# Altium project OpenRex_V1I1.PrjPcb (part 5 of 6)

## Sheet [28] - PWR IN, MECH, DOC.SchDoc
size A2; DocumentNumber: 28; SheetNumber: 28; SheetTotal: 31
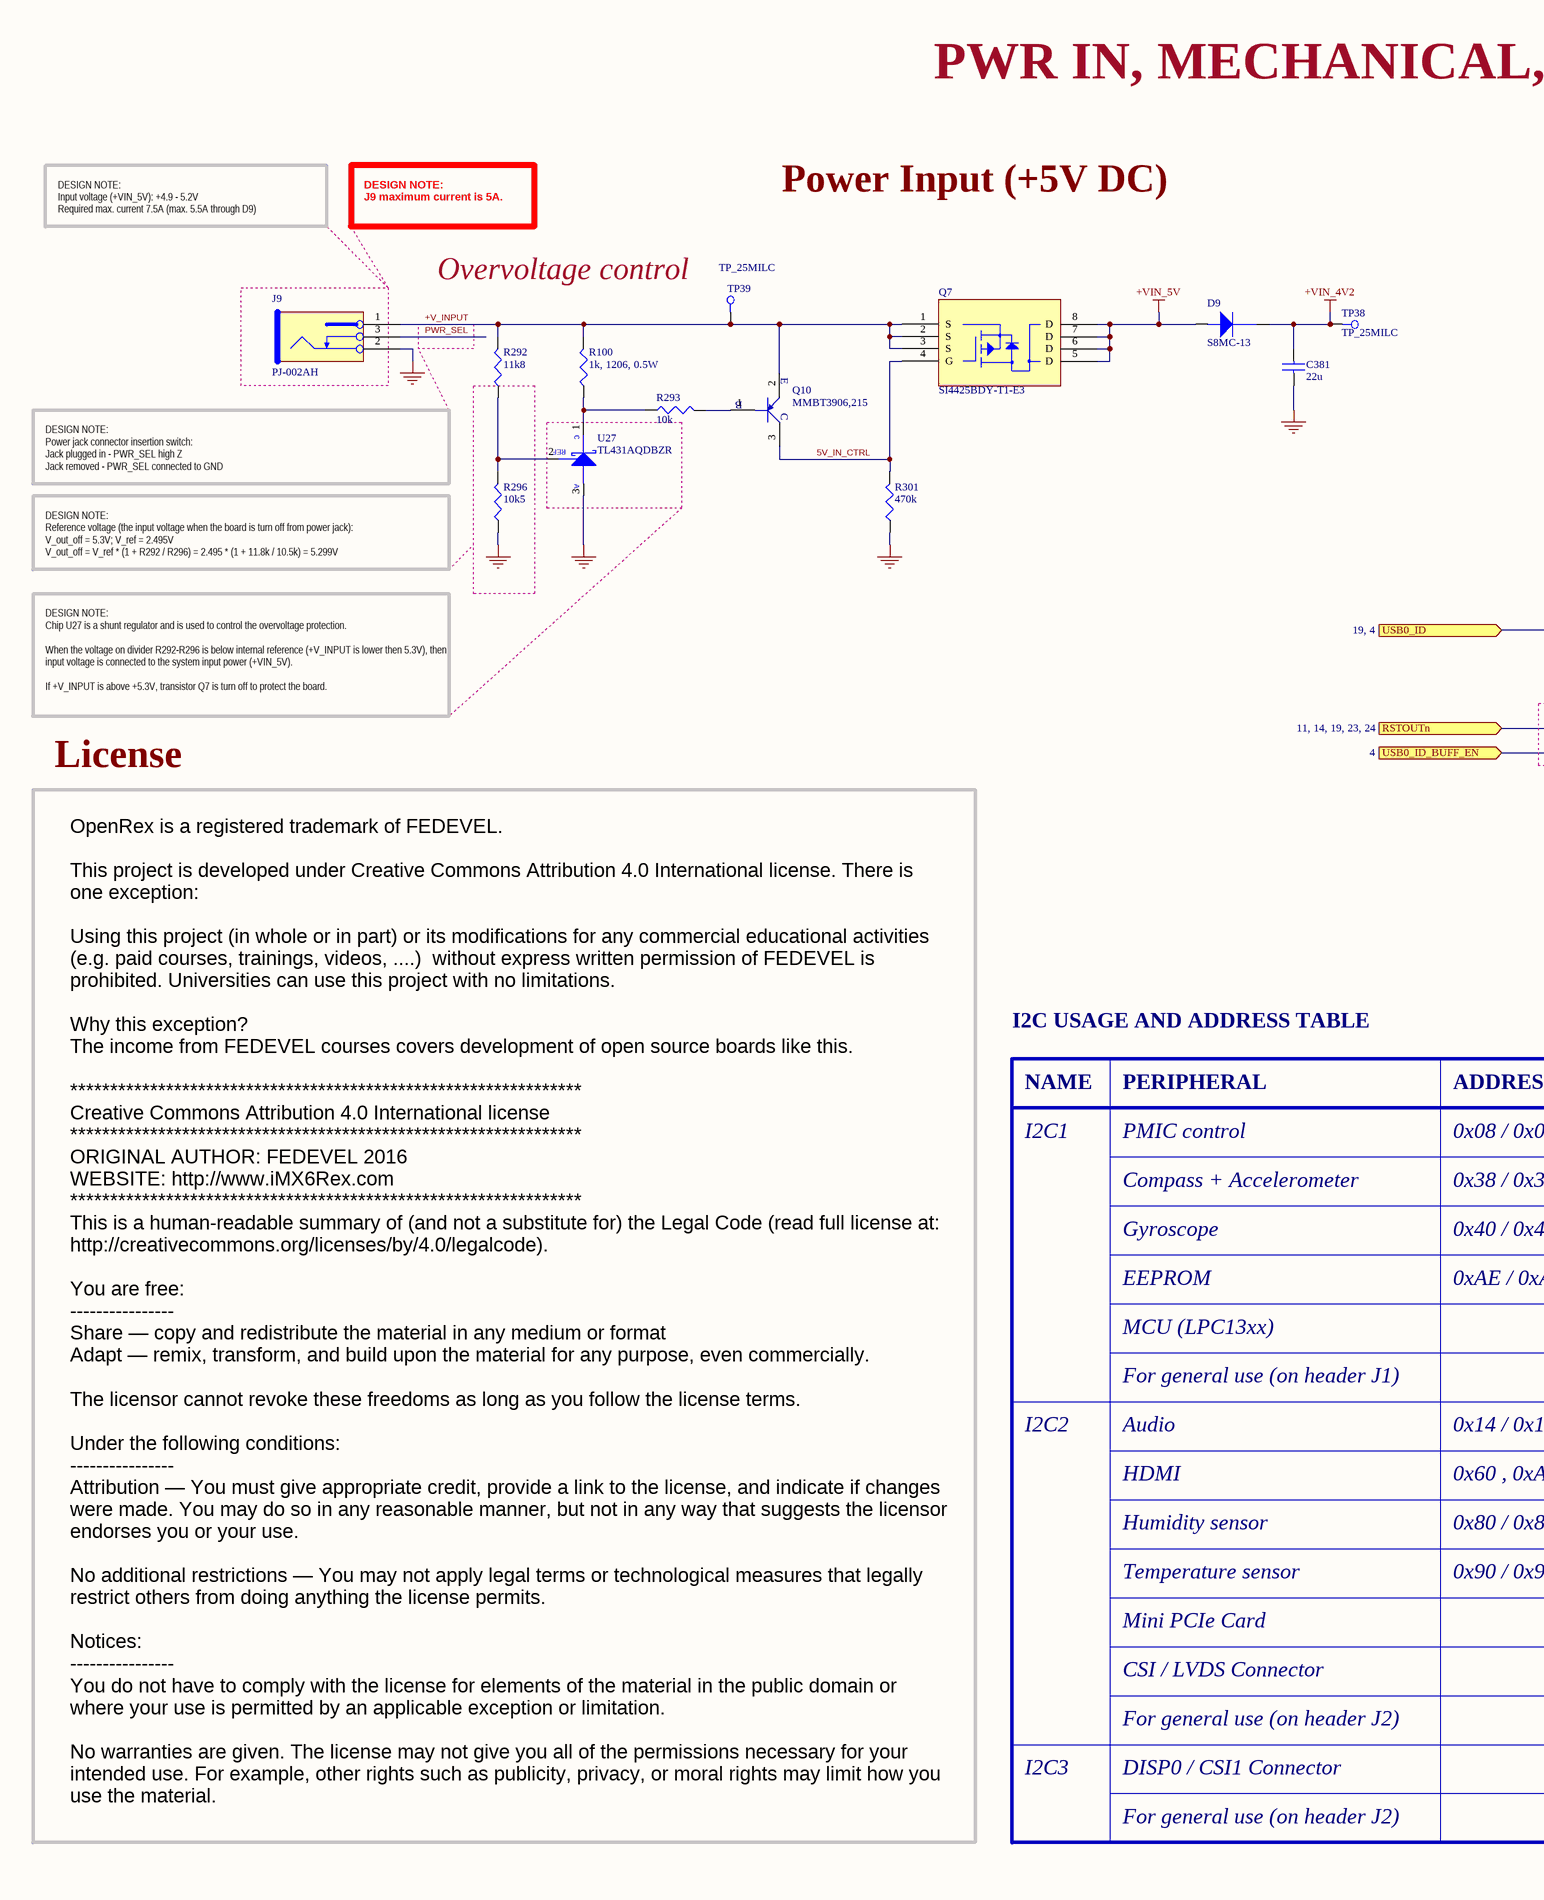
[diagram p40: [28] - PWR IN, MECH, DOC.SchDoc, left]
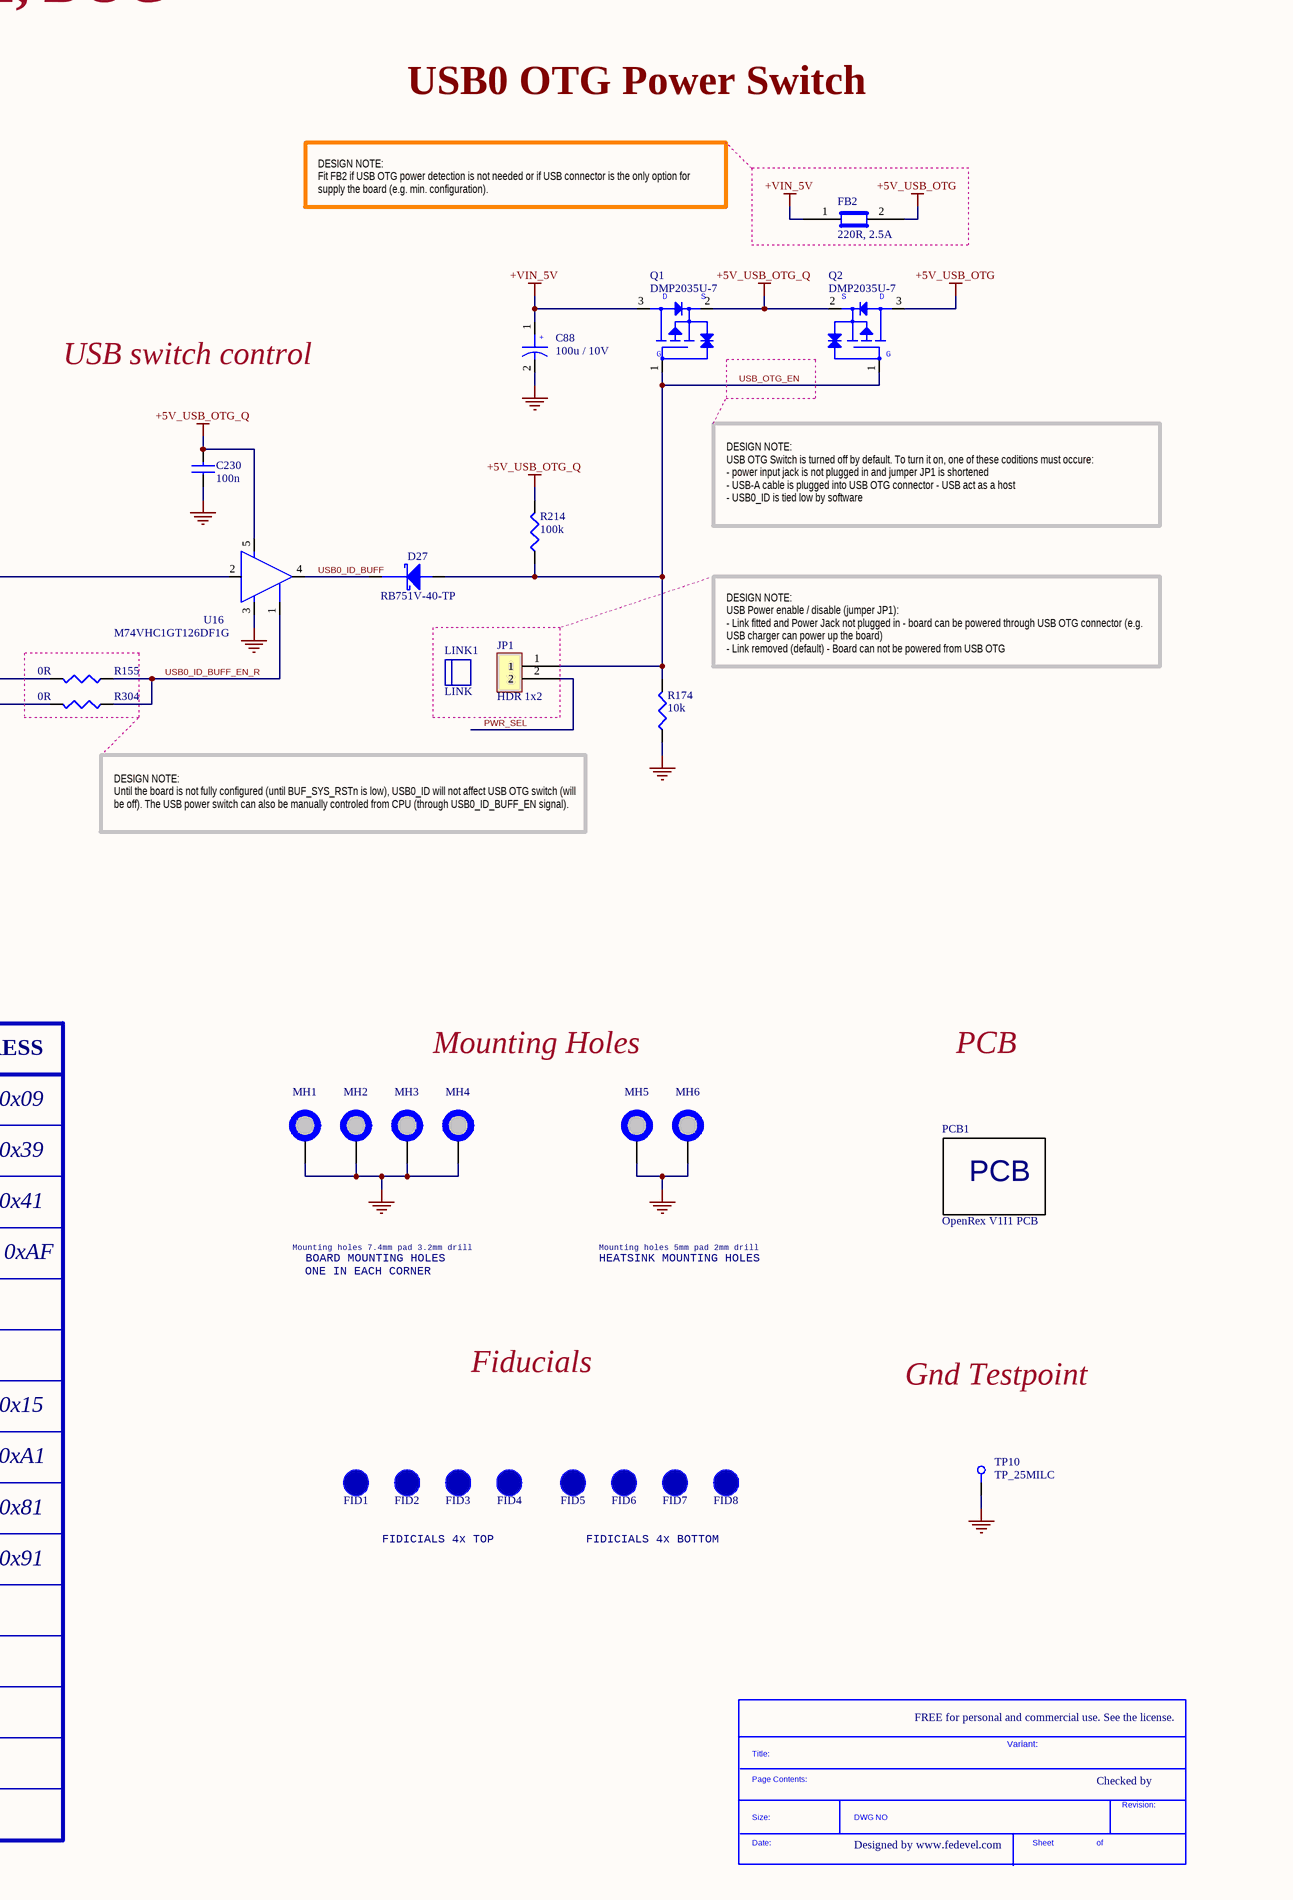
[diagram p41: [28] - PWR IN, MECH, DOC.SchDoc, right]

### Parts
(Parts that share a designator on the sheet are numbered #1, #2 ... from top to bottom, then left to right.)
*#24  SDTitleBlock  (value not drawn)  (graphical)
C88  100u / 10V  [C2312]
C230  100n  [C0402]
C381  22u  [C0603]
D9  S8MC-13  [SMC]
D27  RB751V-40-TP  [SOD323]
FB2  220R, 2.5A  [C0603]
FID1  FID_1MM_SMALL  [FID_40X52D]  (value not drawn)  (no BOM)
FID2  FID_1MM_SMALL  [FID_40X52D]  (value not drawn)  (no BOM)
FID3  FID_1MM_SMALL  [FID_40X52D]  (value not drawn)  (no BOM)
FID4  FID_1MM_SMALL  [FID_40X52D]  (value not drawn)  (no BOM)
FID5  FID_1MM_SMALL  [FID_40X52D]  (value not drawn)  (no BOM)
FID6  FID_1MM_SMALL  [FID_40X52D]  (value not drawn)  (no BOM)
FID7  FID_1MM_SMALL  [FID_40X52D]  (value not drawn)  (no BOM)
FID8  FID_1MM_SMALL  [FID_40X52D]  (value not drawn)  (no BOM)
J9  PJ-002AH  [POWER_JACK_5.5_2.1MM_NS_v1.1]
JP1  HDR 1x2  [HDR_1x2_2.54MM]
LINK1  LINK  (mechanical)
MH1  MH_7.4MMC_3.2MMD  [MH_7.4MMD_3.2MMD]  (value not drawn)  (no BOM)
MH2  MH_7.4MMC_3.2MMD  [MH_7.4MMD_3.2MMD]  (value not drawn)  (no BOM)
MH3  MH_7.4MMC_3.2MMD  [MH_7.4MMD_3.2MMD]  (value not drawn)  (no BOM)
MH4  MH_7.4MMC_3.2MMD  [MH_7.4MMD_3.2MMD]  (value not drawn)  (no BOM)
MH5  MH_5MMC_2MMD  [MH_5MMD_2MMD]  (value not drawn)  (no BOM)
MH6  MH_5MMC_2MMD  [MH_5MMD_2MMD]  (value not drawn)  (no BOM)
PCB1  OpenRex V1I1 PCB  (mechanical)
Q1  DMP2035U-7  [SOT-23-3-123]
Q2  DMP2035U-7  [SOT-23-3-123]
Q7  SI4425BDY-T1-E3  [8_SOIC_3.9MM]
Q10  MMBT3906,215  [SOT-23-3-123]
R100  1k, 1206, 0.5W  [R1206]
R155  0R  [R0402]
R174  10k  [R0402]
R214  100k  [R0402]
R292  11k8  [R0402]
R293  10k  [R0402]
R296  10k5  [R0402]
R301  470k  [R0402]
R304  0R  [R0402]
TP10  TP_25MILC  [TP_25C]  (no BOM)
TP38  TP_25MILC  [TP_25C]  (no BOM)
TP39  TP_25MILC  [TP_25C]  (no BOM)
U16  M74VHC1GT126DF1G  [SC70_5]
U27  TL431AQDBZR  [SOT-23-3-123]

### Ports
RSTOUTn (see 11, 14, 19, 23, 24), USB0_ID (see 19, 4), USB0_ID_BUFF_EN (in, see 4)

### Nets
+5V_USB_OTG: FB2.2 Q2.3
+5V_USB_OTG_Q: C230.2 Q1.2 Q2.2 R214.2 U16.5(VCC)
+VIN_4V2: C381.1 D9.1(Cathode) TP38.1
+VIN_5V: C88.1 D9.2(Anode) FB2.1 Q1.3 Q7.5(D) Q7.6(D) Q7.7(D) Q7.8(D)
GND: C88.2 C230.1 C381.2 J9.2 MH1.1 MH2.1 MH3.1 MH4.1 MH5.1 MH6.1 R174.1 R296.1 R301.1 TP10.1 U16.3(GND) U27.3(ANODE)
5V_IN_CTRL: Q7.4(G) Q10.3(C) R301.2
+V_INPUT: J9.1 Q7.1(S) Q7.2(S) Q7.3(S) Q10.2(E) R100.2 R292.2 TP39.1
PWR_SEL: J9.3 JP1.2
RSTOUTn: R155.2 ; port RSTOUTn
USB0_ID: U16.2(I) ; port USB0_ID
USB0_ID_BUFF: D27.1(cathode) U16.4(O)
USB0_ID_BUFF_EN: R304.2 ; port USB0_ID_BUFF_EN
USB0_ID_BUFF_EN_R: R155.1 R304.1 U16.1(OE#)
USB_OTG_EN: D27.2(ANODE) JP1.1 Q1.1 Q2.1 R174.2 R214.1
NetQ10_1: Q10.1(B) R293.2
NetR100_1: R100.1 R293.1 U27.1(cathode)
NetR292_1: R292.1 R296.2 U27.2(REF)

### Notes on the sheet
- PWR IN, MECHANICAL, DOC
- Power Input (+5V DC)
- USB0 OTG Power Switch
- DESIGN NOTE:
  Input voltage (+VIN_5V): +4.9 - 5.2V
  Required max. current 7.5A (max. 5.5A through D9)
- DESIGN NOTE:
  J9 maximum current is 5A.
- DESIGN NOTE:
  Fit FB2 if USB OTG power detection is not needed or if USB connector is the only option for supply the board (e.g. min. configuration).
- (near TP39) Overvoltage control
- USB switch control
- DESIGN NOTE:
  Power jack connector insertion switch:
  Jack plugged in - PWR_SEL high Z
  Jack removed - PWR_SEL connected to GND
- DESIGN NOTE:
  Reference voltage (the input voltage when the board is turn off from power jack):
  V_out_off = 5.3V; V_ref = 2.495V
  V_out_off = V_ref * (1 + R292 / R296) = 2.495 * (1 + 11.8k / 10.5k) = 5.299V
- DESIGN NOTE:
  USB OTG Switch is turned off by default. To turn it on, one of these coditions must occure:
  - power input jack is not plugged in and jumper JP1 is shortened
  - USB-A cable is plugged into USB OTG connector - USB act as a host
  - USB0_ID is tied low by software
- DESIGN NOTE:
  Chip U27 is a shunt regulator and is used to control the overvoltage protection.
  When the voltage on divider R292-R296 is below internal reference (+V_INPUT is lower then 5.3V), then input voltage is connected to the system input power (+VIN_5V).
  If +V_INPUT is above +5.3V, transistor Q7 is turn off to protect the board.
- DESIGN NOTE:
  USB Power enable / disable (jumper JP1):
  - Link fitted and Power Jack not plugged in - board can be powered through USB OTG connector (e.g. USB charger can power up the board)
  - Link removed (default) - Board can not be powered from USB OTG
- License
- DESIGN NOTE:
  Until the board is not fully configured (until BUF_SYS_RSTn is low), USB0_ID will not affect USB OTG switch (will be off). The USB power switch can also be manually controled from CPU (through USB0_ID_BUFF_EN signal).
- I2C USAGE AND ADDRESS TABLE
- NAME
- PERIPHERAL
- ADDRESS
- Mounting Holes
- PCB
- I2C1
- Compass + Accelerometer
- PMIC control
- 0x38 / 0x39
- 0x08 / 0x09
- Gyroscope
- 0x40 / 0x41
- EEPROM
- 0xAE / 0xAF
- Mounting holes 7.4mm pad 3.2mm drill
- BOARD MOUNTING HOLES
- ONE IN EACH CORNER
- HEATSINK MOUNTING HOLES
- Mounting holes 5mm pad 2mm drill
- MCU (LPC13xx)
- I2C2
- For general use (on header J1)
- Audio
- 0x14 / 0x15
- Fiducials
- Gnd Testpoint
- HDMI
- 0x60 , 0xA1
- Humidity sensor
- 0x80 / 0x81
- FIDICIALS 4x TOP
- FIDICIALS 4x BOTTOM
- Temperature sensor
- 0x90 / 0x91
- Mini PCIe Card
- CSI / LVDS Connector
- For general use (on header J2)
- FREE for personal and commercial use. See the license.
- I2C3
- DISP0 / CSI1 Connector
- Variant:
- Checked by
- OpenRex is a registered trademark of FEDEVEL.
  This project is developed under Creative Commons Attribution 4.0 International license. There is one exception:
  Using this project (in whole or in part) or its modifications for any commercial educational activities (e.g. paid courses, trainings, videos, ....)  without express written permission of FEDEVEL is prohibited. Universities can use this project with no limitations.
  Why this exception?
  The income from FEDEVEL courses covers development of open source boards like this.
  ****************************************************************
  Creative Commons Attribution 4.0 International license
  ****************************************************************
  ORIGINAL AUTHOR: FEDEVEL 2016
  WEBSITE: http://www.iMX6Rex.com
  ****************************************************************
  This is a human-readable summary of (and not a substitute for) the Legal Code (read full license at:
  http://creativecommons.org/licenses/by/4.0/legalcode).
  You are free:
  ----------------
  Share — copy and redistribute the material in any medium or format
  Adapt — remix, transform, and build upon the material for any purpose, even commercially.
  The licensor cannot revoke these freedoms as long as you follow the license terms.
  Under the following conditions:
  ----------------
  Attribution — You must give appropriate credit, provide a link to the license, and indicate if changes were made. You may do so in any reasonable manner, but not in any way that suggests the licensor endorses you or your use.
  No additional restrictions — You may not apply legal terms or technological measures that legally restrict others from doing anything the license permits.
  Notices:
  ----------------
  You do not have to comply with the license for elements of the material in the public domain or where your use is permitted by an applicable exception or limitation.
  No warranties are given. The license may not give you all of the permissions necessary for your intended use. For example, other rights such as publicity, privacy, or moral rights may limit how you use the material.
- Designed by www.fedevel.com

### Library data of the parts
C88 = TPSC107K010R0150: CAP TANT 100UF 10V 10% 2312; Manufacturer: AVX Corporation; Manufacturer Size Code: C; Capacitance: 100µF; ESR (Equivalent Series Resistance): 150 mOhm; Type: Molded; .Creator: MM
C230 = C1005X5R1H104K: CAP CER .10UF 50V X5R 10% 0402; Manufacturer: TDK Corporation; Capacitance: 0.1µF; Value: 100nF; .Checked PCB: used
C381 = C1608X5R0J226M080AC: CAP CER 22UF 6.3V 20% X5R 0603; Manufacturer: TDK Corporation; Capacitance: 22µF; .Creator: MM
D9 = S8MC-13: DIODE GEN PURP 1KV 8A SMC; Manufacturer: Diodes Incorporated; Diode Type: Standard; Voltage - DC Reverse (Vr) (Max): 1000V (1kV); Voltage - Forward (Vf) (Max) @ If: 985mV @ 8A; Speed: Standard Recovery >500ns, > 200mA (Io); Current - Reverse Leakage @ Vr: 10µA @ 1000V; Capacitance @ Vr, F: 40pF @ 4V, 1MHz; .Checked PCB: MM
D27 = RB751V-40-TP: DIODE SCHTKY 30MA 30V SOD-323; Manufacturer: Micro Commercial Co; Diode Type: Schottky; Voltage - Forward (Vf) (Max) @ If: 370mV @ 1mA; Speed: Small Signal =< 200mA (Io), Any Speed; Current - Reverse Leakage @ Vr: 500nA @ 30V; Capacitance @ Vr, F: 2pF @ 1V, 1MHz; .Checked PCB: used
FB2 = BLM18SG221TN1D: FERRITE CHIP 220 OHM 2500MA 0603; Manufacturer: Murata Electronics North America; Impedance @ Frequency: 220 Ohm @ 100MHz; DC Resistance (DCR): 40 mOhm Max; Filter Type: Differential Mode - Single; Number of Lines: 1; .Checked PCB: used
FID1-FID8 = FID_1MM_SMALL: Fiducial 40mil Diameter, 52mil Mask
J9 = PJ-002AH_v1.1: CONN PWR JACK 2.1X5.5MM HIGH CUR; Manufacturer: CUI Inc; .Checked PCB: MM; Mating connector: 2.1mm ID, 5.5mm OD; Gender: Male; Number of Positions/Contacts: 2 Conductors, 3 Contacts; Internal Switch(s): Single Switch, Normally Closed; Shielding: Unshielded; Voltage - Rated: 24VDC; Current Rating: 5A
JP1 = 68001-202HLF: BERGSTIK II .100" SR STRAIGHT; Manufacturer: FCI; Connector Type: Header, Unshrouded; Number of Positions: 2; Number of Positions Loaded: All; Pitch: 0.100" (2.54mm); .Checked PCB: used
LINK1 = QPC02SXGN-RC: CONN JUMPER SHORTING .100" GOLD; Manufacturer: Sullins Connector Solutions; Gender: Female Sockets; Number of Positions or Pins (Grid): 2 (1 x 2); Pitch: 0.100" (2.54mm); .Checked SCH: used
MH1-MH4 = MH_7.4MMC_3.2MMD: Mounting Hole 7.4mm Diameter, 3.2mm Drill; .Creator: MM
MH5 MH6 = MH_5MMC_2MMD: Mounting Hole 5mm Diameter, 2mm Drill; .Creator: MM
PCB1 = PCB_OpenRex_V1I1: .Creator: MM
Q1 Q2 = DMP2035U-7: MOSFET P-CH 20V 3.6A SOT-23; Manufacturer: Diodes Incorporated; FET Type: MOSFET P-Channel, Metal Oxide; FET Feature: Logic Level Gate; Current - Continuous Drain (Id) @ 25°C: 3.6A (Ta); Rds On (Max) @ Id, Vgs: 35 mOhm @ 4A, 4.5V; Vgs(th) (Max) @ Id: 1V @ 250µA; Gate Charge (Qg) @ Vgs: 15.4nC @ 4.5V; Input Capacitance (Ciss) @ Vds: 1610pF @ 10V; Power - Max: 810mW; .Checked PCB: MM
Q7 = SI4425BDY-T1-E3: MOSFET P-CH 30V 8.8A 8-SOIC; Manufacturer: Vishay Siliconix; FET Type: MOSFET P-Channel, Metal Oxide; FET Feature: Logic Level Gate; Current - Continuous Drain (Id) @ 25°C: 8.8A (Ta); Rds On (Max) @ Id, Vgs: 12 mOhm @ 11.4A, 10V; Vgs(th) (Max) @ Id: 3V @ 250µA; Gate Charge (Qg) @ Vgs: 100nC @ 10V; Power - Max: 1.5W; .Checked PCB: MM
Q10 = MMBT3906,215: TRANS PNP 40V 0.2A SOT23; Manufacturer: NXP Semiconductors; Current - Collector (Ic) (Max): 200mA; Vce Saturation (Max) @ Ib, Ic: 400mV @ 5mA, 50mA; DC Current Gain (hFE) (Min) @ Ic, Vce: 100 @ 10mA, 1V; Power - Max: 250mW; Frequency - Transition: 250MHz; .Checked PCB: MM
R100 = RNCP1206FTD1K00: RES SMD 1K OHM 1% 1/2W 1206; Manufacturer: Stackpole Electronics Inc; Power (Watts): 0.5W, 1/2W; Temperature Coefficient: ±100ppm/°C; .Checked PCB: MM
R155 R304 = RC0402JR-070RL: RES 0.0 OHM 1/16W 0402 SMD; Manufacturer: Yageo; Resistance (Ohms): 0.0; Power (Watts): 0.063W, 1/16W; Tolerance: Jumper; .Checked PCB: used
R174 R293 = RC0402FR-0710KL: RES 10.0K OHM 1/16W 1% 0402 SMD; Manufacturer: Yageo; Power (Watts): 0.063W, 1/16W; .Checked PCB: used; Temperature Coefficient: ±100ppm/°C
R214 = RMCF0402FT100K: RES 100K OHM 1/16W 1% 0402 SMD; Manufacturer: Stackpole Electronics Inc; Power (Watts): 0.063W, 1/16W; .Checked PCB: used; Temperature Coefficient: ±100ppm/°C
R292 = CRCW040211K8FKED: RES 11.8K OHM 1/16W 1% 0402 SMD; Manufacturer: Vishay Dale; Power (Watts): 0.063W, 1/16W; Temperature Coefficient: ±100ppm/°C; .Checked PCB: RF
R296 = CRCW040210K5FKED: RES 10.5K OHM 1/16W 1% 0402 SMD; Manufacturer: Vishay/Dale; Power (Watts): 0.063W, 1/16W; .Checked PCB: used; Temperature Coefficient: ±100ppm/°C
R301 = CRCW0402470KFKED: RES 470K OHM 1/16W 1% 0402 SMD; Manufacturer: Vishay Dale; Power (Watts): 0.063W, 1/16W; Temperature Coefficient: ±100ppm/°C; .Checked PCB: MM
TP10 TP38 TP39 = TP_25MILC: Test Point 25mil
U16 = M74VHC1GT126DF1G: IC BUFF CMOS LVL/SFTR N-I SOT353; Manufacturer: ON Semiconductor; Logic Type: Buffer/Line Driver, Non-Inverting; Number of Elements: 1; Current - Output High, Low: 8mA, 8mA; Voltage - Supply: 3 V ~ 5.5 V; .Checked PCB: MM
U27 = TL431AQDBZR: IC VREF SHUNT ADJ SOT23-3; Manufacturer: Texas Instruments; Output Type: Adjustable; Voltage - Output (Min/Fixed): 2.495V; Voltage - Output (Max): 36V; Current - Output: 100mA; Tolerance: ±1%; Current - Cathode: 700µA; .Checked PCB: MM

## Sheet [22] - SD CARD, SPI, FLASH, EEPROM,.SchDoc
size A2; DocumentNumber: 22; SheetNumber: 22; SheetTotal: 31
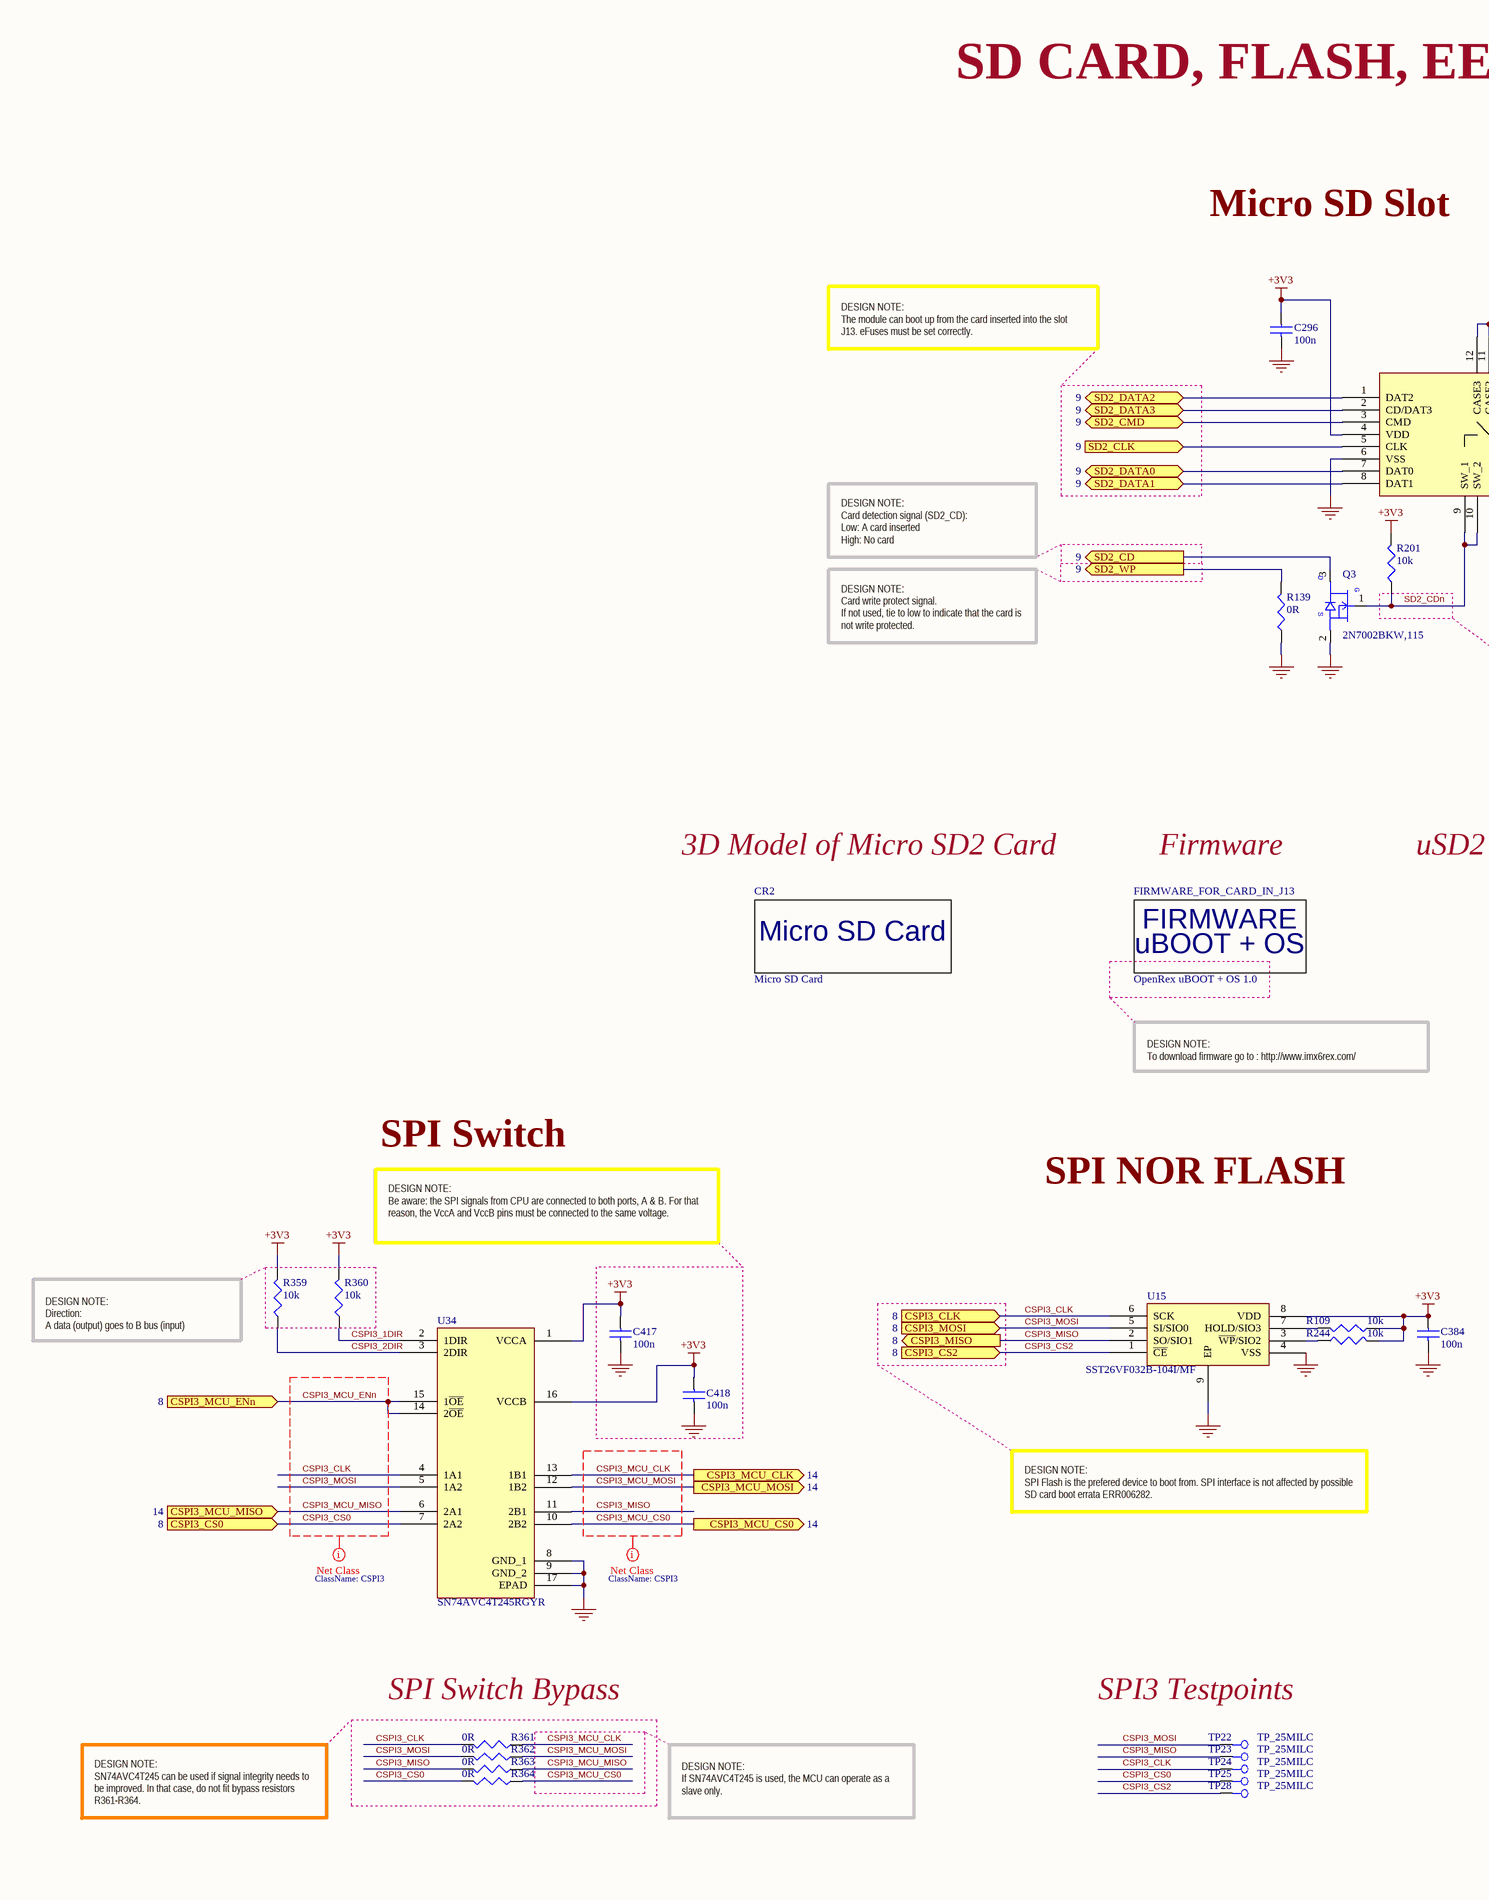
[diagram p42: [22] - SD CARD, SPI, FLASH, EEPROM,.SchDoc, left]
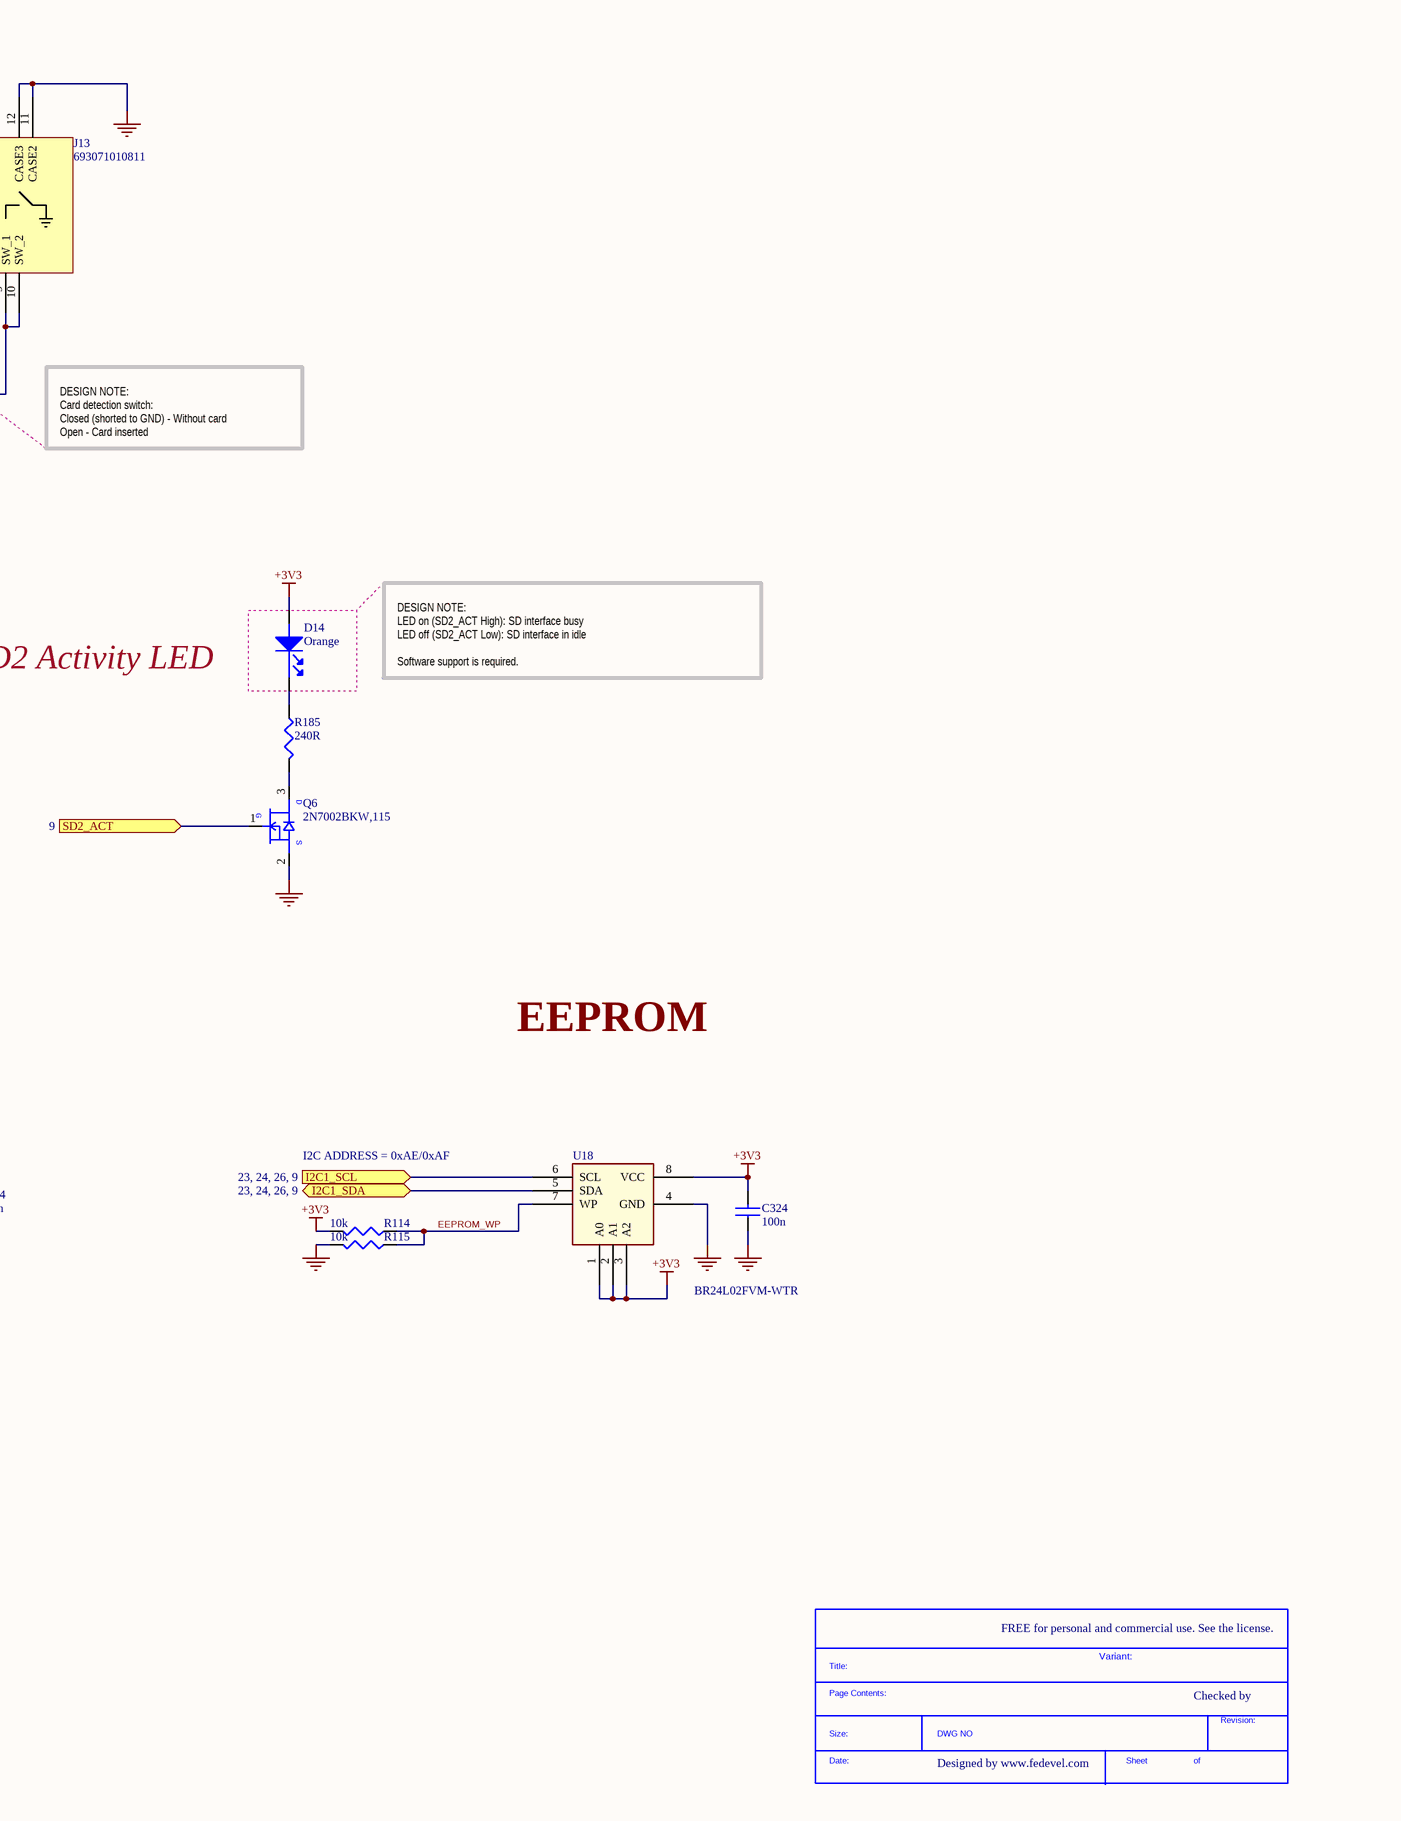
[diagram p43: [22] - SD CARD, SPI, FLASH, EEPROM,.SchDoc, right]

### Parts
(Parts that share a designator on the sheet are numbered #1, #2 ... from top to bottom, then left to right.)
*#25  SDTitleBlock  (value not drawn)  (graphical)
C296  100n  [C0402]
C324  100n  [C0402]
C384  100n  [C0402]
C417  100n  [C0402]
C418  100n  [C0402]
CR2  Micro SD Card  [Micro_SD_card]  (no BOM)
D14  Orange  [LED_0603]
FIRMWARE_FOR_CARD_IN_J13  OpenRex uBOOT + OS 1.0  (mechanical)
J13  693071010811  [693071010811]
Q3  2N7002BKW,115  [SC70_SOT323]
Q6  2N7002BKW,115  [SC70_SOT323]
R109  10k  [R0402]
R114  10k  [R0402]
R115  10k  [R0402]
R139  0R  [R0402]
R185  240R  [R0402]
R201  10k  [R0402]
R244  10k  [R0402]
R359  10k  [R0402]
R360  10k  [R0402]
R361  0R  [R0402]
R362  0R  [R0402]
R363  0R  [R0402]
R364  0R  [R0402]
TP22  TP_25MILC  [TP_25C]  (no BOM)
TP23  TP_25MILC  [TP_25C]  (no BOM)
TP24  TP_25MILC  [TP_25C]  (no BOM)
TP25  TP_25MILC  [TP_25C]  (no BOM)
TP28  TP_25MILC  [TP_25C]  (no BOM)
U15  SST26VF032B-104I/MF  [WSON8_6X5MM]
U18  BR24L02FVM-WTR  [MSOP8 _SMALLER]
U34  SN74AVC4T245RGYR  [RGY (R-PVQFN-N16)]

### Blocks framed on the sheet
SPI Switch Bypass: R361-R364

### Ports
CSPI3_CLK (see 8), CSPI3_CS0 (in, see 8), CSPI3_CS2 (in, see 8), CSPI3_MCU_CLK (out, see 14), CSPI3_MCU_CS0 (out, see 14), CSPI3_MCU_ENn (in, see 8), CSPI3_MCU_MISO (in, see 14), CSPI3_MCU_MOSI (out, see 14), CSPI3_MISO (out, see 8), CSPI3_MOSI (see 8), I2C1_SCL (see 23, 24, 26, 9), I2C1_SDA (bidir, see 23, 24, 26, 9), SD2_ACT (in, see 9), SD2_CD (out, see 9), SD2_CLK (in, see 9), SD2_CMD (bidir, see 9), SD2_DATA0 (bidir, see 9), SD2_DATA1 (bidir, see 9), SD2_DATA2 (bidir, see 9), SD2_DATA3 (bidir, see 9), SD2_WP (out, see 9)

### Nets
+3V3: C296.1 C324.2 C384.1 C417.1 C418.1 D14.2(ANODE) J13.4(VDD) R109.1 R114.2 R201.2 R244.2 R359.2 R360.2 U15.8(VDD) U18.1(A0) U18.2(A1) U18.3(A2) U18.8(VCC) U34.1(VCCA) U34.16(VCCB)
GND: C296.2 C324.1 C384.2 C417.2 C418.2 J13.6(VSS) J13.11(CASE2) J13.12(CASE3) Q3.2(SOURCE) Q6.2(SOURCE) R115.2 R139.1 U15.4(VSS) U15.9(EP) U18.4(GND) U34.8(GND_1) U34.9(GND_2) U34.17(EPAD)
CSPI3_1DIR: R360.1 U34.2(1DIR)
CSPI3_2DIR: R359.1 U34.3(2DIR)
CSPI3_CLK: R361.2 TP24.1 U15.6(SCK) U34.4(1A1) ; port CSPI3_CLK
CSPI3_CS0: R364.2 TP25.1 U34.7(2A2) ; port CSPI3_CS0
CSPI3_CS2: TP28.1 U15.1(~{CE}) ; port CSPI3_CS2
CSPI3_MCU_CLK: R361.1 U34.13(1B1) ; port CSPI3_MCU_CLK
CSPI3_MCU_CS0: R364.1 U34.10(2B2) ; port CSPI3_MCU_CS0
CSPI3_MCU_ENn: U34.14(2~{OE}) U34.15(1~{OE}) ; port CSPI3_MCU_ENn
CSPI3_MCU_MISO: R363.1 U34.6(2A1) ; port CSPI3_MCU_MISO
CSPI3_MCU_MOSI: R362.1 U34.12(1B2) ; port CSPI3_MCU_MOSI
CSPI3_MISO: R363.2 TP23.1 U15.2(SO/SIO1) U34.11(2B1) ; port CSPI3_MISO
CSPI3_MOSI: R362.2 TP22.1 U15.5(SI/SIO0) U34.5(1A2) ; port CSPI3_MOSI
EEPROM_WP: R114.1 R115.1 U18.7(WP)
I2C1_SCL: U18.6(SCL) ; port I2C1_SCL
I2C1_SDA: U18.5(SDA) ; port I2C1_SDA
SD2_ACT: Q6.1(GATE) ; port SD2_ACT
SD2_CD: Q3.3(DRAIN) ; port SD2_CD
SD2_CDn: J13.9(SW_1) J13.10(SW_2) Q3.1(GATE) R201.1
SD2_CLK: J13.5(CLK) ; port SD2_CLK
SD2_CMD: J13.3(CMD) ; port SD2_CMD
SD2_DATA0: J13.7(DAT0) ; port SD2_DATA0
SD2_DATA1: J13.8(DAT1) ; port SD2_DATA1
SD2_DATA2: J13.1(DAT2) ; port SD2_DATA2
SD2_DATA3: J13.2(CD/DAT3) ; port SD2_DATA3
SD2_WP: R139.2 ; port SD2_WP
NetD14_1: D14.1(cathode) R185.1
NetQ6_3: Q6.3(DRAIN) R185.2
NetR109_2: R109.2 U15.7(HOLD/SIO3)
NetR244_1: R244.1 U15.3(~{WP}/SIO2)

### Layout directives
net class CSPI3: CSPI3_CLK, CSPI3_CS0, CSPI3_MCU_CLK, CSPI3_MCU_CS0, CSPI3_MCU_ENn, CSPI3_MCU_MISO, CSPI3_MCU_MOSI, CSPI3_MISO, CSPI3_MOSI

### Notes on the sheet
- SD CARD, FLASH, EEPROM
- Micro SD Slot
- DESIGN NOTE:
  The module can boot up from the card inserted into the slot J13. eFuses must be set correctly.
- DESIGN NOTE:
  Card detection signal (SD2_CD):
  Low: A card inserted
  High: No card
- DESIGN NOTE:
  Card write protect signal.
  If not used, tie to low to indicate that the card is not write protected.
- DESIGN NOTE:
  Card detection switch:
  Closed (shorted to GND) - Without card
  Open - Card inserted
- 3D Model of Micro SD2 Card
- Firmware
- uSD2 Activity LED
- DESIGN NOTE:
  LED on (SD2_ACT High): SD interface busy
  LED off (SD2_ACT Low): SD interface in idle
  Software support is required.
- DESIGN NOTE:
  To download firmware go to : http://www.imx6rex.com/
- SPI Switch
- SPI NOR FLASH
- EEPROM
- DESIGN NOTE:
  Be aware: the SPI signals from CPU are connected to both ports, A & B. For that reason, the VccA and VccB pins must be connected to the same voltage.
- I2C ADDRESS = 0xAE/0xAF
- DESIGN NOTE:
  Direction:
  A data (output) goes to B bus (input)
- DESIGN NOTE:
  SPI Flash is the prefered device to boot from. SPI interface is not affected by possible SD card boot errata ERR006282.
- SPI3 Testpoints
- FREE for personal and commercial use. See the license.
- Variant:
- Checked by
- DESIGN NOTE:
  SN74AVC4T245 can be used if signal integrity needs to be improved. In that case, do not fit bypass resistors R361-R364.
- DESIGN NOTE:
  If SN74AVC4T245 is used, the MCU can operate as a slave only.
- Designed by www.fedevel.com

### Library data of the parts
C296 C324 C384 C417 C418 = C1005X5R1H104K: as C230 on sheet [28] - PWR IN, MECH, DOC
CR2 = Card_Micro_SD: Card Micro SD; .Creator: MM
D14 = LO L29K-H2K1-24-Z: LED SMARTLED ORANGE 606NM 0603; Manufacturer: OSRAM Opto Semiconductors Inc; Millicandela Rating: 6.3mcd; Voltage - Forward (Vf) Typ: 1.8V; Current - Test: 2mA; Wavelength - Peak: 610nm; Viewing Angle: 160°; Lens Type: Diffused; Lens Style/Size: Rectangle with Flat Top, 1.3mm x 0.8mm; Luminous Flux @ Current - Test: 25 mlm; .Checked PCB: used
FIRMWARE_FOR_CARD_IN_J13 = FIRMWARE_OpenRex_uBOOT_OS 1.0: .Creator: MM
J13 = 693071010811: CONN MICRO SD 8 POS SMD; Manufacturer: Wurth Electronics Inc; Card Type: Secure Digital - microSD™; Number of Positions: 9 (8 + 1); Connector Type: Connector and Ejector; Insertion, Removal Method: Push In, Push Out; .Creator: MM; .Checked PCB: used
Q3 Q6 = 2N7002BKW,115: MOSFET N-CH 60V 310MA SOT323; Manufacturer: NXP Semiconductors; FET Type: MOSFET N-Channel, Metal Oxide; FET Feature: Logic Level Gate; Rds On (Max) @ Id, Vgs: 1.6 Ohm @ 500mA, 10V; Vgs(th) (Max) @ Id: 2.1V @ 250µA; Gate Charge (Qg) @ Vgs: 0.6nC @ 4.5V; Input Capacitance (Ciss) @ Vds: 50pF @ 10V; Power - Max: 275mW; .Checked PCB: used
R109 R114 R115 R201 R244 R359 R360 = RC0402FR-0710KL: as R174 on sheet [28] - PWR IN, MECH, DOC
R139 R361-R364 = RC0402JR-070RL: as R155 on sheet [28] - PWR IN, MECH, DOC
R185 = RMCF0402FT240R: RES TF 240 OHM 1% 0.0625W 0402; Manufacturer: Stackpole Electronics Inc; Resistance (Ohms): 240; Power (Watts): 0.063W, 1/16W; .Checked PCB: used; Temperature Coefficient: ±100ppm/°C
TP22-TP25 TP28 = TP_25MILC: Test Point 25mil
U15 = SST26VF032B-104I/MF: IC FLASH 32MBIT; Manufacturer: Microchip Technology; Memory Size: 32M (4M x 8); Speed: 104MHz; Interface: SQI, SPI; Voltage - Supply: 2.7 V ~ 3.6 V; .Creator: MM; .Checked PCB: MM, paper model not chceked
U18 = BR24L02FVM-WTR: IC EEPROM 2KBIT 400KHZ 8MSOP; Manufacturer: Rohm Semiconductor; Format - Memory: EEPROMs - Serial; Memory Size: 2K (256 x 8); Interface: I²C, 2-Wire Serial; Voltage - Supply: 1.8 V ~ 5.5 V; .Checked PCB: used
U34 = SN74AVC4T245RGYR: IC BUS TRANSCVR 4BIT 16QFN; Manufacturer: Texas Instruments; Logic Function: Translator, Bidirectional, 3-State; Input Type: Voltage; Data Rate: 380Mbps; Number of Channels: 2; Differential - Input:Output: No/No; Propagation Delay (Max): 2.9ns; Voltage - Supply: 1.2 V ~ 3.6 V; .Creator: MM

## Sheet [23] - SENSORS, CAN, IR.SchDoc
size A2; DocumentNumber: 23; SheetNumber: 23; SheetTotal: 31
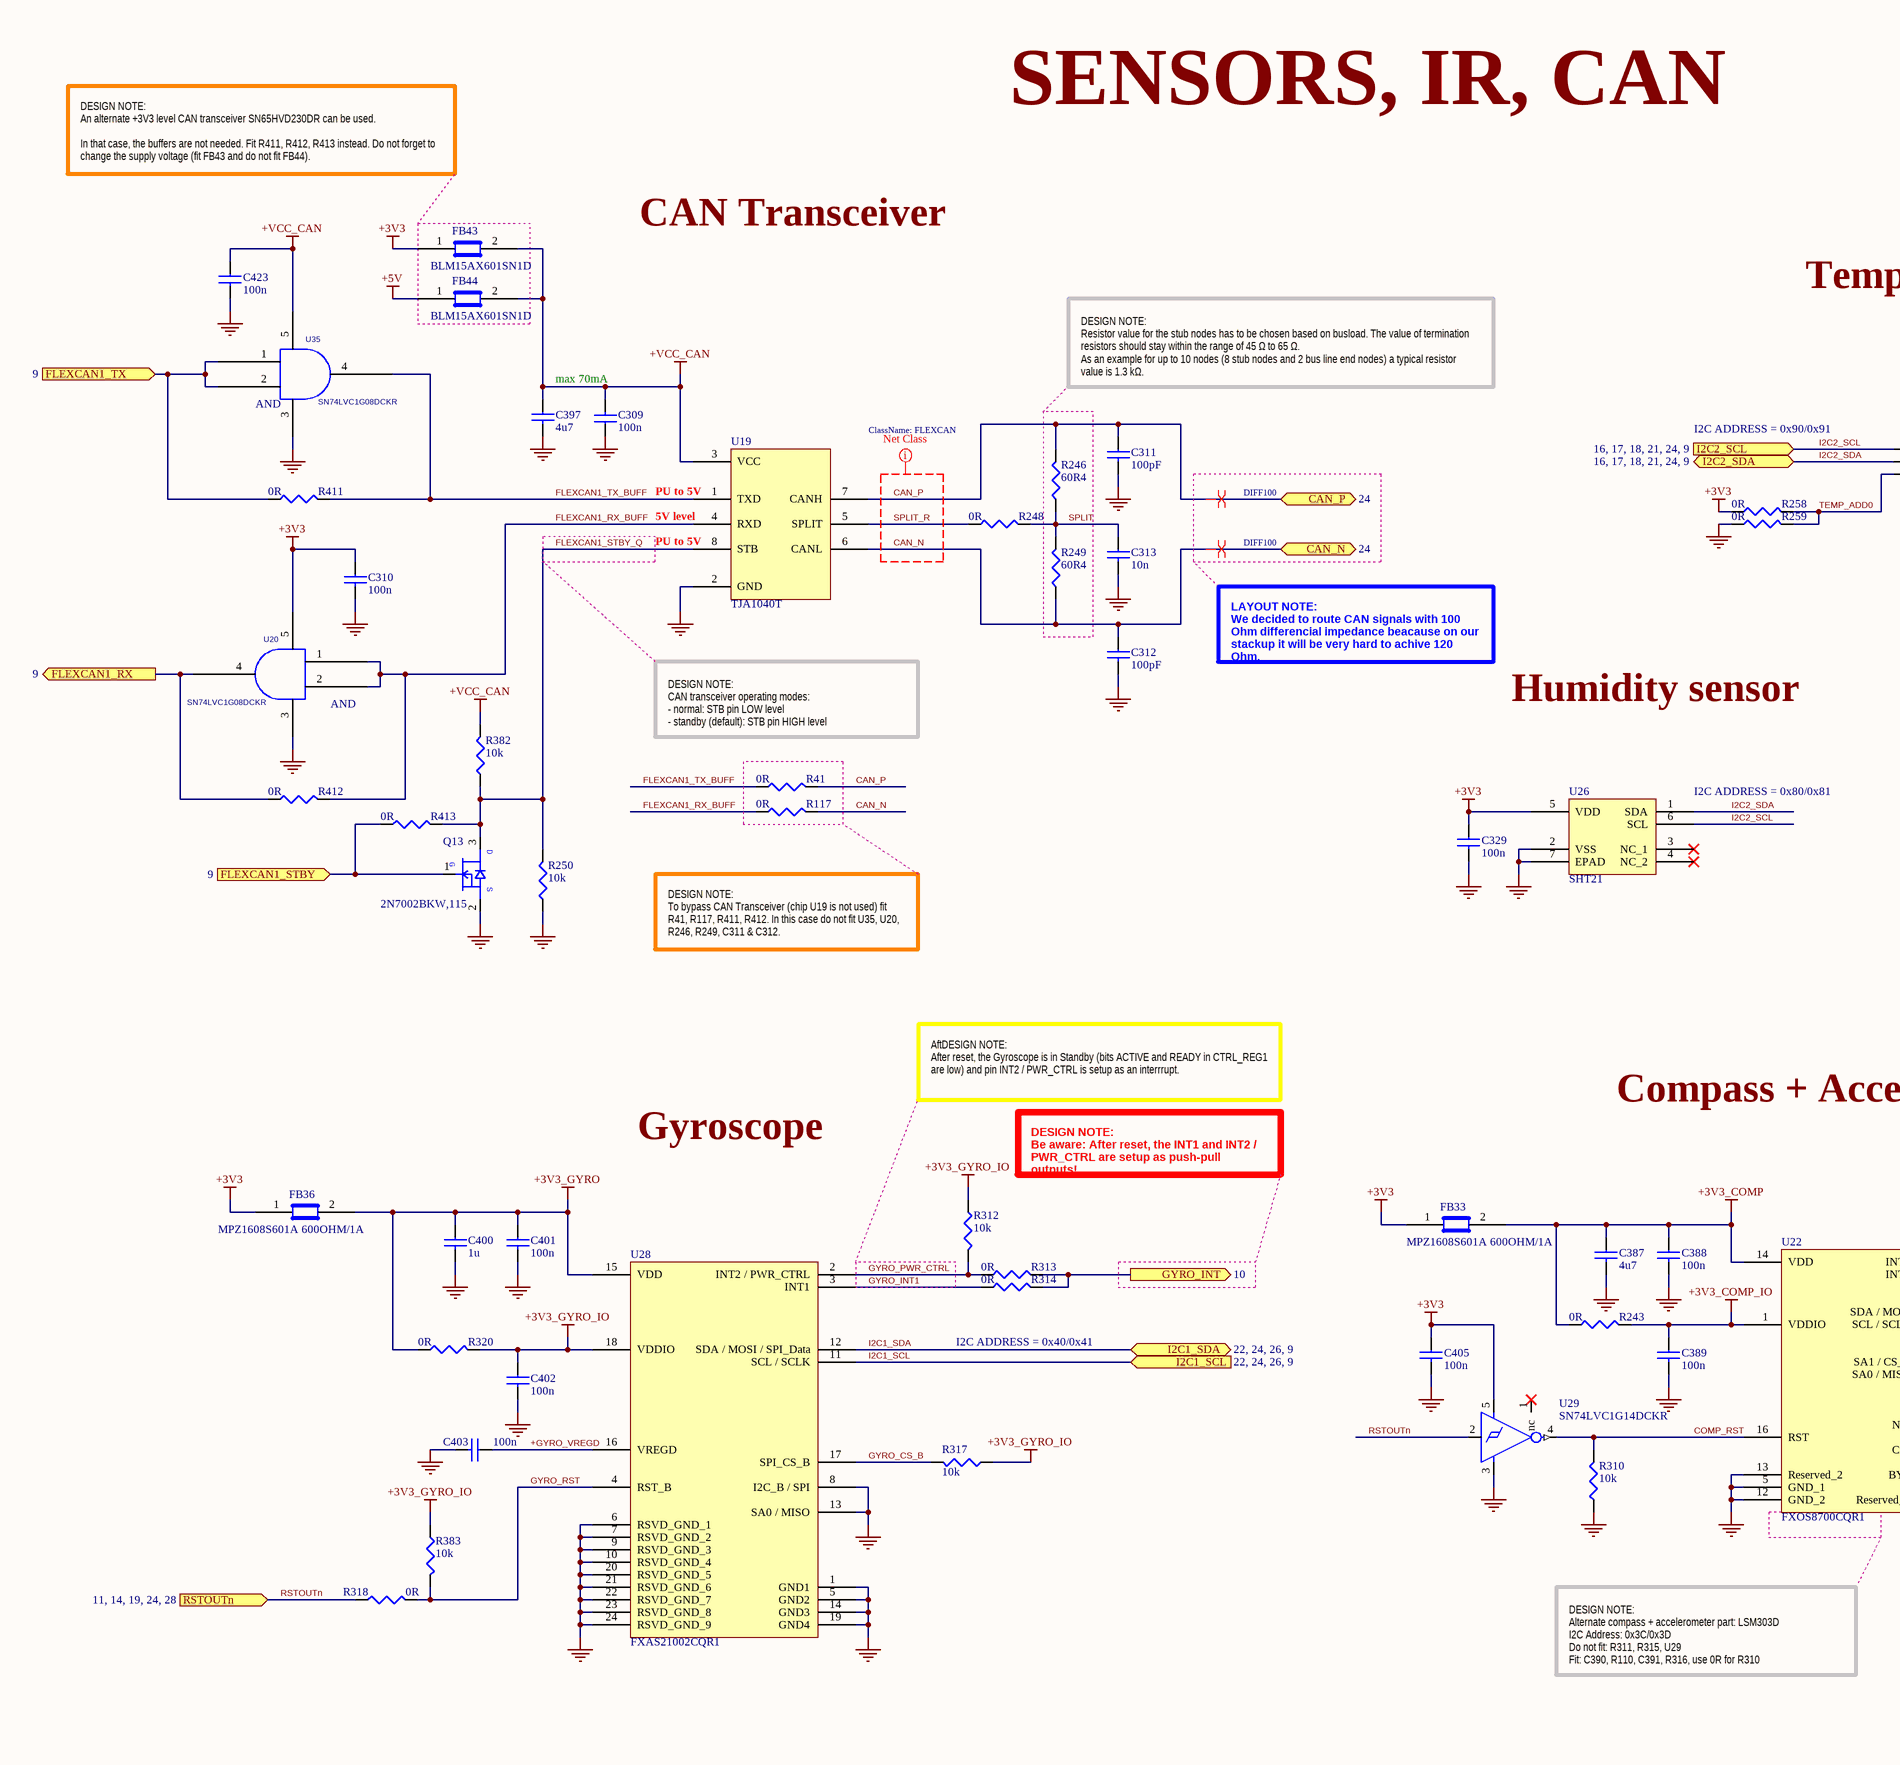
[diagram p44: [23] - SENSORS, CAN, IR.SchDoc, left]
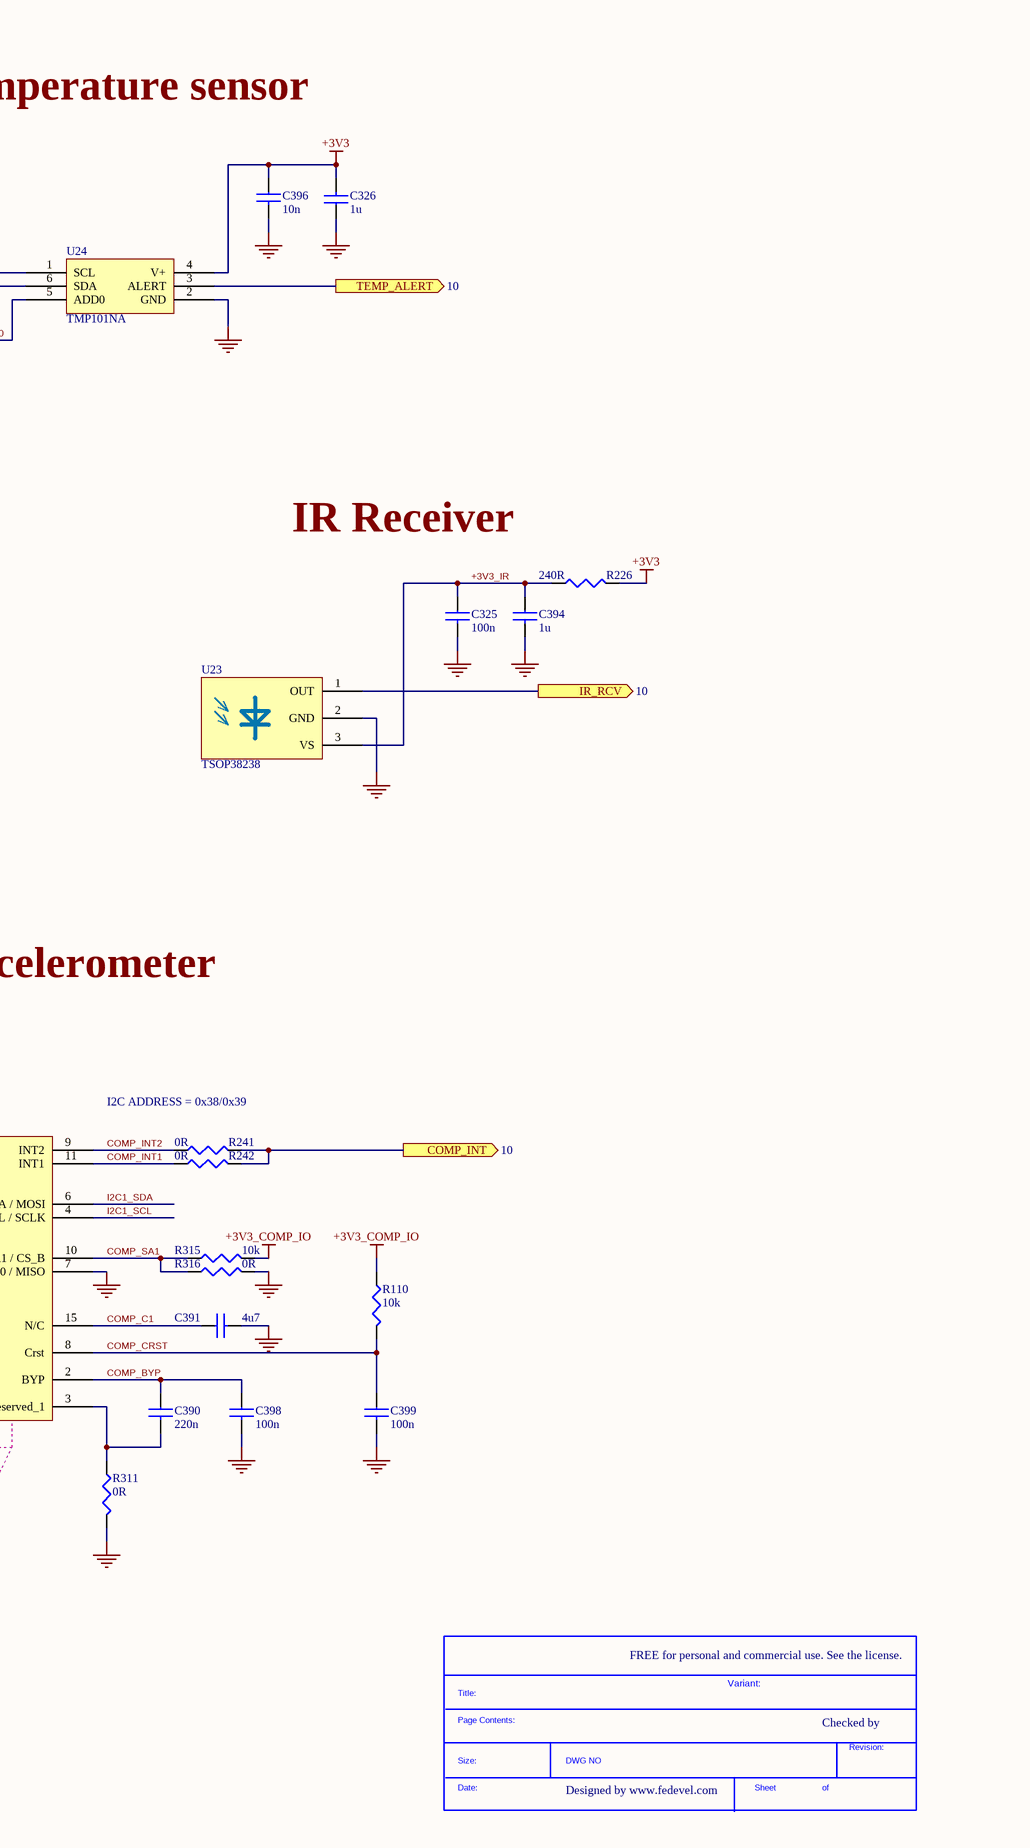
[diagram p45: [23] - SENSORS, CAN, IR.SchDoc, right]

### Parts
(Parts that share a designator on the sheet are numbered #1, #2 ... from top to bottom, then left to right.)
*#26  SDTitleBlock  (value not drawn)  (graphical)
C309  100n  [C0402]
C310  100n  [C0402]
C311  100pF  [C0402]
C312  100pF  [C0402]
C313  10n  [C0402]
C325  100n  [C0402]
C326  1u  [C0402]
C329  100n  [C0402]
C387  4u7  [C0402]
C388  100n  [C0402]
C389  100n  [C0402]
C390  220n  [C0402]
C391  4u7  [C0402]
C394  1u  [C0402]
C396  10n  [C0402]
C397  4u7  [C0402]
C398  100n  [C0402]
C399  100n  [C0402]
C400  1u  [C0402]
C401  100n  [C0402]
C402  100n  [C0402]
C403  100n  [C0402]
C405  100n  [C0402]
C423  100n  [C0402]
FB33  MPZ1608S601A 600OHM/1A  [C0603]
FB36  MPZ1608S601A 600OHM/1A  [C0603]
FB43  BLM15AX601SN1D  [C0402]
FB44  BLM15AX601SN1D  [C0402]
Q13  2N7002BKW,115  [SC70_SOT323]
R41  0R  [R0402]
R110  10k  [R0402]
R117  0R  [R0402]
R226  240R  [R0402]
R241  0R  [R0402]
R242  0R  [R0402]
R243  0R  [R0402]
R246  60R4  [R0402]
R248  0R  [R0402]
R249  60R4  [R0402]
R250  10k  [R0402]
R258  0R  [R0402]
R259  0R  [R0402]
R310  10k  [R0402]
R311  0R  [R0402]
R312  10k  [R0402]
R313  0R  [R0402]
R314  0R  [R0402]
R315  10k  [R0402]
R316  0R  [R0402]
R317  10k  [R0402]
R318  0R  [R0402]
R320  0R  [R0402]
R382  10k  [R0402]
R383  10k  [R0402]
R411  0R  [R0402]
R412  0R  [R0402]
R413  0R  [R0402]
U19  TJA1040T  [8_SOIC_3.9MM]
U20  SN74LVC1G08DCKR  [SC70_5]
U22  FXOS8700CQR1  [QFN16_3x3mm]
U23  TSOP38238  [TSOP382]
U24  TMP101NA  [SOT23-6_DBV6]
U26  SHT21  [6_DFN_3mmx3mm]
U28  FXAS21002CQR1  [QFN24_4x4MM]
U29  SN74LVC1G14DCKR  [SC70_5]
U35  SN74LVC1G08DCKR  [SC70_5]

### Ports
CAN_N (bidir, see 24), CAN_P (bidir, see 24), COMP_INT (out, see 10), FLEXCAN1_RX (out, see 9), FLEXCAN1_STBY (in, see 9), FLEXCAN1_TX (in, see 9), GYRO_INT (out, see 10), I2C1_SCL (see 22, 24, 26, 9), I2C1_SDA (bidir, see 22, 24, 26, 9), I2C2_SCL (see 16, 17, 18, 21, 24, 9), I2C2_SDA (bidir, see 16, 17, 18, 21, 24, 9), IR_RCV (out, see 10), RSTOUTn (see 11, 14, 19, 24, 28), TEMP_ALERT (out, see 10)

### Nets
+3V3: C310.1 C326.2 C329.1 C396.1 C405.1 FB33.1 FB36.1 FB43.1 R226.2 R258.1 U20.5(VCC) U24.4(V+) U26.5(VDD) U29.5(NC1)
+3V3_COMP: C387.1 C388.1 FB33.2 R243.1 U22.14(VDD)
+3V3_COMP_IO: C389.1 R110.1 R243.2 R315.2 U22.1(VDDIO)
+3V3_GYRO: C400.1 C401.1 FB36.2 R320.1 U28.15(VDD)
+3V3_GYRO_IO: C402.1 R312.1 R317.1 R320.2 R383.1 U28.18(VDDIO)
+5V: FB44.1
+VCC_CAN: C309.2 C397.1 C423.1 FB43.2 FB44.2 R382.2 U19.3(VCC) U35.5(VCC)
GND: C309.1 C310.2 C311.2 C312.2 C313.2 C325.2 C326.1 C329.2 C387.2 C388.2 C389.2 C391.2 C394.2 C396.2 C397.2 C398.2 C399.2 C400.2 C401.2 C402.2 C403.2 C405.2 C423.2 Q13.2(SOURCE) R250.1 R259.1 R310.1 R311.2 R316.2 U19.2(GND) U20.3(GND) U22.5(GND_1) U22.7(SA0_/_MISO) U22.12(GND_2) U22.13(Reserved_2) U23.2(GND) U24.2(GND) U26.2(VSS) U26.7(EPAD) U28.1(GND1) U28.5(GND2) U28.6(RSVD_GND_1) U28.7(RSVD_GND_2) U28.8(I2C_B_/_SPI) U28.9(RSVD_GND_3) U28.10(RSVD_GND_4) U28.13(SA0_/_MISO) U28.14(GND3) U28.19(GND4) U28.20(RSVD_GND_5) U28.21(RSVD_GND_6) U28.22(RSVD_GND_7) U28.23(RSVD_GND_8) U28.24(RSVD_GND_9) U29.3(GND) U35.3(GND)
+3V3_IR: C325.1 C394.1 R226.1 U23.3(VS)
+GYRO_VREGD: C403.1 U28.16(VREGD)
CAN_N: C312.1 R117.2 R249.1 U19.6(CANL) ; port CAN_N
CAN_P: C311.1 R41.2 R246.2 U19.7(CANH) ; port CAN_P
COMP_BYP: C390.1 C398.1 U22.2(BYP)
COMP_C1: C391.1 U22.15(N/C)
COMP_CRST: C399.1 R110.2 U22.8(Crst)
COMP_INT: R241.2 R242.2 ; port COMP_INT
COMP_INT1: R242.1 U22.11(INT1)
COMP_INT2: R241.1 U22.9(INT2)
COMP_RST: R310.2 U22.16(RST) U29.4(O)
COMP_SA1: R315.1 R316.1 U22.10(SA1_/_CS_B)
FLEXCAN1_RX: R412.1 U20.4(Y) ; port FLEXCAN1_RX
FLEXCAN1_RX_BUFF: R117.1 R412.2 U19.4(RXD) U20.1(A) U20.2(B)
FLEXCAN1_STBY: Q13.1(GATE) R413.1 ; port FLEXCAN1_STBY
FLEXCAN1_STBY_Q: Q13.3(DRAIN) R250.2 R382.1 R413.2 U19.8(STB)
FLEXCAN1_TX: R411.1 U35.1(A) U35.2(B) ; port FLEXCAN1_TX
FLEXCAN1_TX_BUFF: R41.1 R411.2 U19.1(TXD) U35.4(Y)
GYRO_CS_B: R317.2 U28.17(SPI_CS_B)
GYRO_INT: R313.2 R314.2 ; port GYRO_INT
GYRO_INT1: R314.1 U28.3(INT1)
GYRO_PWR_CTRL: R312.2 R313.1 U28.2(INT2_/_PWR_CTRL)
GYRO_RST: R318.2 R383.2 U28.4(RST_B)
I2C1_SCL: U22.4(SCL_/_SCLK) U28.11(SCL_/_SCLK) ; port I2C1_SCL
I2C1_SDA: U22.6(SDA_/_MOSI) U28.12(SDA_/_MOSI_/_SPI_Data) ; port I2C1_SDA
I2C2_SCL: U24.1(SCL) U26.6(SCL) ; port I2C2_SCL
I2C2_SDA: U24.6(SDA) U26.1(SDA) ; port I2C2_SDA
IR_RCV: U23.1(OUT) ; port IR_RCV
RSTOUTn: R318.1 U29.2(I) ; port RSTOUTn
SPLIT: C313.1 R246.1 R248.2 R249.2
SPLIT_R: R248.1 U19.5(SPLIT)
TEMP_ADD0: R258.2 R259.2 U24.5(ADD0)
TEMP_ALERT: U24.3(ALERT) ; port TEMP_ALERT
NetC390_2: C390.2 R311.1 U22.3(Reserved_1)

Not connected (* = marked no-connect by the designer): U26 3(NC_1)* 4(NC_2)*; U29 1(nc)*

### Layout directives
net class FLEXCAN: CAN_N, CAN_P, SPLIT_R
differential pair; net class DIFF100: CAN_N, CAN_P

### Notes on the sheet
- SENSORS, IR, CAN
- DESIGN NOTE:
  An alternate +3V3 level CAN transceiver SN65HVD230DR can be used.
  In that case, the buffers are not needed. Fit R411, R412, R413 instead. Do not forget to change the supply voltage (fit FB43 and do not fit FB44).
- CAN Transceiver
- Temperature sensor
- max 70mA
- DESIGN NOTE:
  Resistor value for the stub nodes has to be chosen based on busload. The value of termination resistors should stay within the range of 45 Ω to 65 Ω.
  As an example for up to 10 nodes (8 stub nodes and 2 bus line end nodes) a typical resistor value is 1.3 kΩ.
- I2C ADDRESS = 0x90/0x91
- (near U19) PU to 5V
- (near U19) 5V level
- LAYOUT NOTE:
  We decided to route CAN signals with 100 Ohm differencial impedance beacause on our stackup it will be very hard to achive 120 Ohm.
- DESIGN NOTE:
  CAN transceiver operating modes:
  - normal: STB pin LOW level
  - standby (default): STB pin HIGH level
- Humidity sensor
- IR Receiver
- (near U26) I2C ADDRESS = 0x80/0x81
- DESIGN NOTE:
  To bypass CAN Transceiver (chip U19 is not used) fit R41, R117, R411, R412. In this case do not fit U35, U20, R246, R249, C311 & C312.
- AftDESIGN NOTE:
  After reset, the Gyroscope is in Standby (bits ACTIVE and READY in CTRL_REG1 are low) and pin INT2 / PWR_CTRL is setup as an interrrupt.
- Compass + Accelerometer
- Gyroscope
- DESIGN NOTE:
  Be aware: After reset, the INT1 and INT2 / PWR_CTRL are setup as push-pull outputs!
- I2C ADDRESS = 0x38/0x39
- I2C ADDRESS = 0x40/0x41
- DESIGN NOTE:
  Alternate compass + accelerometer part: LSM303D
  I2C Address: 0x3C/0x3D
  Do not fit: R311, R315, U29
  Fit: C390, R110, C391, R316, use 0R for R310
- FREE for personal and commercial use. See the license.
- Variant:
- Checked by
- Designed by www.fedevel.com

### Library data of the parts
C309 C310 C325 C329 C388 C389 C398 C399 C401-C403 C405 C423 = C1005X5R1H104K: as C230 on sheet [28] - PWR IN, MECH, DOC
C311 C312 = C1005C0G1H101J: CAP CER 100PF 50V 5% NP0 0402; Manufacturer: TDK Corporation; Temperature Coefficient: C0G, NP0; .Checked PCB: used
C313 C396 = C1005X7R1H103K: CAP CER 10000PF 50V 10% X7R 0402; Manufacturer: TDK Corporation; Value: 10nF; .Checked PCB: used
C326 C394 C400 = C1005X5R1C105K: CAP CER 1.0UF 16V X5R 0402; Manufacturer: TDK Corporation; Capacitance: 1.0µF; Value: 1uF; .Checked PCB: used; Tolerance: ±10%
C387 C391 C397 = C1005X5R1A475M: CAP CER 4.7UF 10V 20% X5R 0402; Manufacturer: TDK Corporation; Capacitance: 4.7µF; .Checked PCB: used
C390 = C1005X5R1E224M: CAP CER .22UF 25V X5R 20% 0402; Manufacturer: TDK Corporation; Capacitance: 0.22µF; Value: 220nF; .Checked PCB: used
FB33 FB36 = MPZ1608S601A: FERRITE CHIP BEAD 600 OHM SMD 1A; Manufacturer: TDK Corporation; Impedance @ Frequency: 600 Ohm @ 100MHz; DC Resistance (DCR): 150 mOhm Max; Filter Type: Differential Mode - Single; Number of Lines: 1; .Checked PCB: used
FB43 FB44 = BLM15AX601SN1D: FERRITE CHIP 600 OHM 0402 420mA; Manufacturer: Murata Electronics North America; .Checked PCB: used; Impedance @ Frequency: 600 Ohm @ 100MHz; DC Resistance (DCR): 340 mOhm Max; Filter Type: Differential Mode - Single; Number of Lines: 1
Q13 = 2N7002BKW,115: as Q3 on sheet [22] - SD CARD, SPI, FLASH, EEPROM,
R41 R117 R241-R243 R248 R258 R259 R311 R313 R314 R316 R318 R320 R411-R413 = RC0402JR-070RL: as R155 on sheet [28] - PWR IN, MECH, DOC
R110 R250 R310 R312 R315 R317 R382 R383 = RC0402FR-0710KL: as R174 on sheet [28] - PWR IN, MECH, DOC
R226 = RMCF0402FT240R: as R185 on sheet [22] - SD CARD, SPI, FLASH, EEPROM,
R246 R249 = RC0402FR-0760R4L: RES SMD 60.4 OHM 1% 1/16W 0402; Manufacturer: Yageo; Resistance (Ohms): 60.4; Power (Watts): 0.063W, 1/16W; Temperature Coefficient: ±100ppm/°C; .Creator: MM
U19 = TJA1040T/CM,118: IC TRANSCEIVER CAN 8SOIC; Manufacturer: NXP Semiconductors; Number of Drivers/Receivers: 1/1; Duplex: Half; Receiver Hysteresis: 70mV; Voltage - Supply: 4.75 V ~ 5.25 V; .Creator: MM
U20 U35 = SN74LVC1G08DCKR: SINGLE POSITIVE AND GATE SC-70; Manufacturer: Texas Instruments; .Checked PCB: used; Number of Inputs: 2; Voltage - Supply: 1.65 V ~ 5.5 V; Number of Circuits: 1; Current - Output High, Low: 32mA, 32mA
U22 = FXOS8700CQR1: SENSOR XTRINSIC 6-AXIS QFN; Manufacturer: Freescale Semiconductor; Sensor Type: Accelerometer, Magnetometer, 3 Axis; Output Type: I²C, SPI; .Checked PCB: MM
U23 = TSOP38238: IC IR RCVR MOD 38KHZ DOME AXIAL; Manufacturer: Vishay Semiconductor Opto Division; Sensing Distance: 45m; B.P.F. Center Frequency: 38.0kHz; Voltage - Supply: 2.5 V ~ 5.5 V; Current - Supply: 450µA; .Creator: MM
U24 = TMP101NA: IC DIGITAL TEMP SENSOR SOT23-6; Manufacturer: Texas Instruments; Manufacturer Part Number: TMP101NA/3K; Function: Temp Monitoring System (Sensor); Sensor Type: Internal; Sensing Temperature: -55°C ~ 125°C; Accuracy: ±3°C(Max); Topology: ADC (Sigma Delta), Register Bank; Output Type: I²C™/SMBus™; Output Alarm: Yes; Output Fan: No; Voltage - Supply: 2.7 V ~ 5.5 V; .Checked PCB: RF(LibOnly), MM; .Checked SCH: RF
U26 = SHT21: SENSIRION - SHT21 - SENSOR, HUMIDITY & TEMP, 3X3MM, 2%; Humidity Range: 0% to 100; Sensitivity: ± 1%; Sensor Output1: Digital; Sensor Terminals: SMD; Response Time: 5; Supply Voltage Min: 2.1; Supply Voltage Max: 3.6; .Creator: MM
U28 = FXAS21002CQR1: GYROSCOPE 3-AXIS 24QFN; Manufacturer: Freescale Semiconductor; Range °/s: ±250°/s, ±500°/s, ±1000°/s, ±2000°/s; Sensitivity: 0.0078°/s/LSB, 0.0156°/s/LSB, 0.0312°/s/LSB, 0.0625°/s/LSB; Typical Bandwidth: 400Hz; Voltage - Supply: 1.95 V ~ 3.6 V; Current - Supply: 2.7mA; Output Type: I²C, SPI; .Checked PCB: MM
U29 = SN74LVC1G14DCKR: IC SGL SCHMT-TRIG INVERT SC70-5; Manufacturer: Texas Instruments; Logic Type: Inverter; Number of Circuits: 1; Voltage - Supply: 1.65 V ~ 5.5 V; Current - Quiescent (Max): 10µA; Current - Output High, Low: 32mA, 32mA; Logic Level - Low: 0.39 V ~ 1.87 V; Logic Level - High: 1.16 V ~ 3.33 V; Max Propagation Delay @ V, Max CL: 5ns @ 5V, 50pF; .Checked PCB: MM, paper model not checked; .Checked SCH: MM

## Sheet [30] - REVISION HISTORY.SchDoc
size A3; DocumentNumber: 30; SheetNumber: 30; SheetTotal: 31
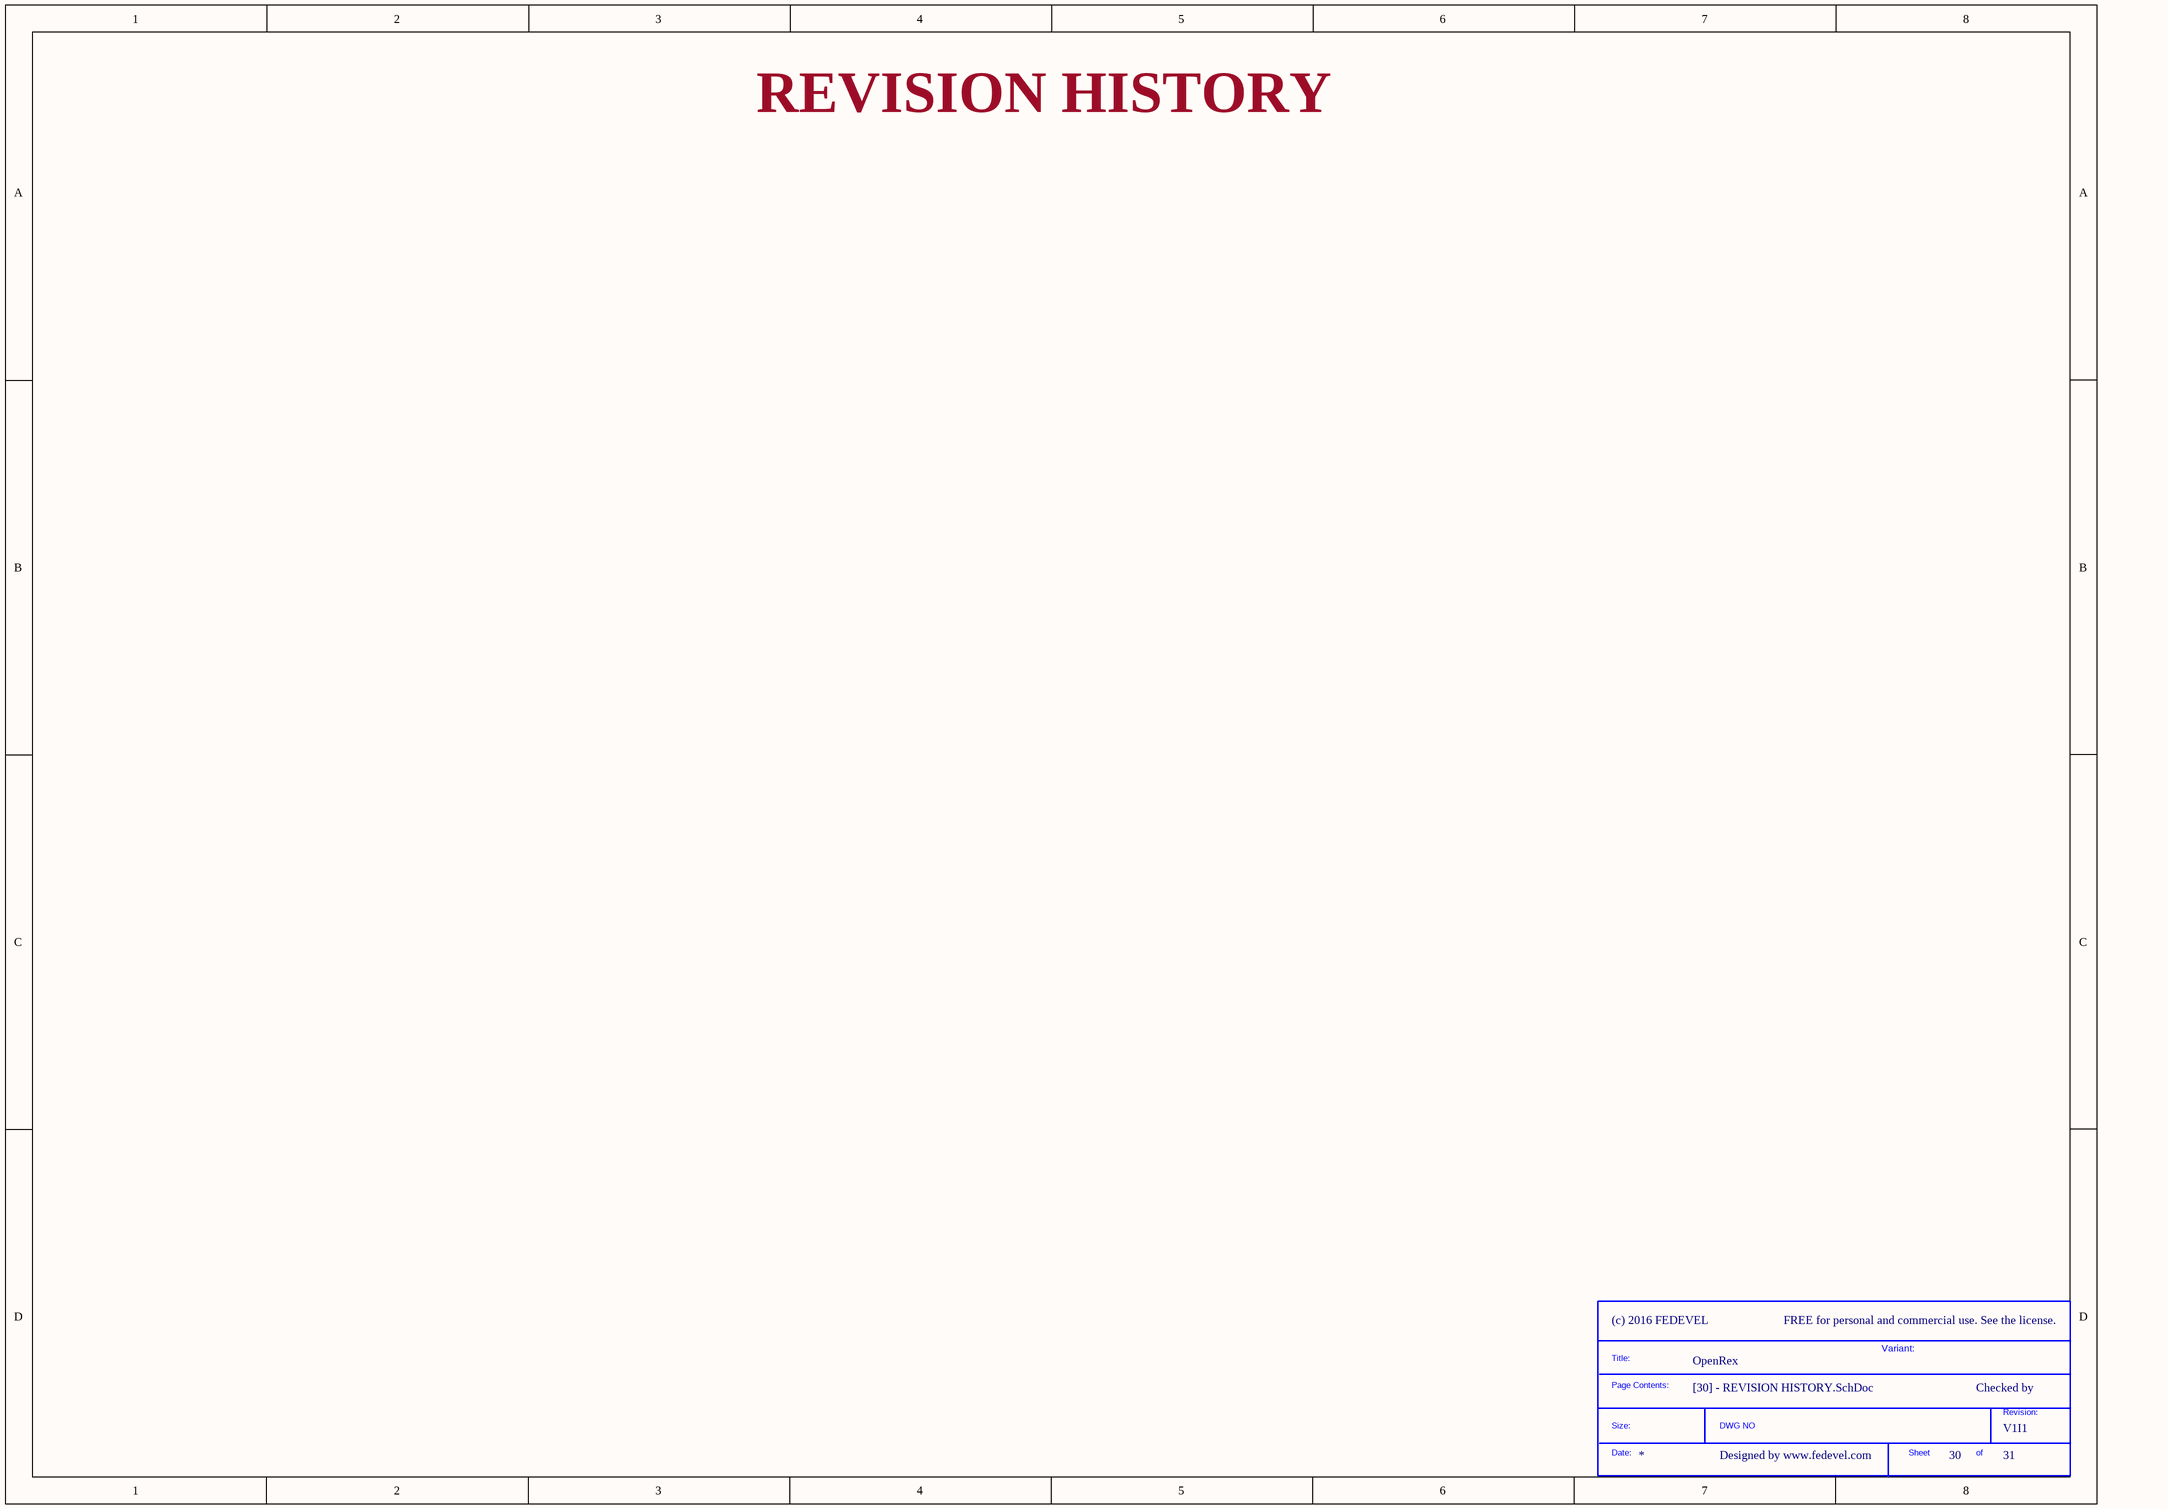
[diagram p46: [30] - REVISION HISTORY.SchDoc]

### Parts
(Parts that share a designator on the sheet are numbered #1, #2 ... from top to bottom, then left to right.)
*#27  SDTitleBlock  (value not drawn)  (graphical)

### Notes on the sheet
- REVISION HISTORY
- FREE for personal and commercial use. See the license.
- Variant:
- Checked by
- Designed by www.fedevel.com

## Sheet [16] - HDMI.SchDoc
size A3; DocumentNumber: 16; SheetNumber: 16; SheetTotal: 31
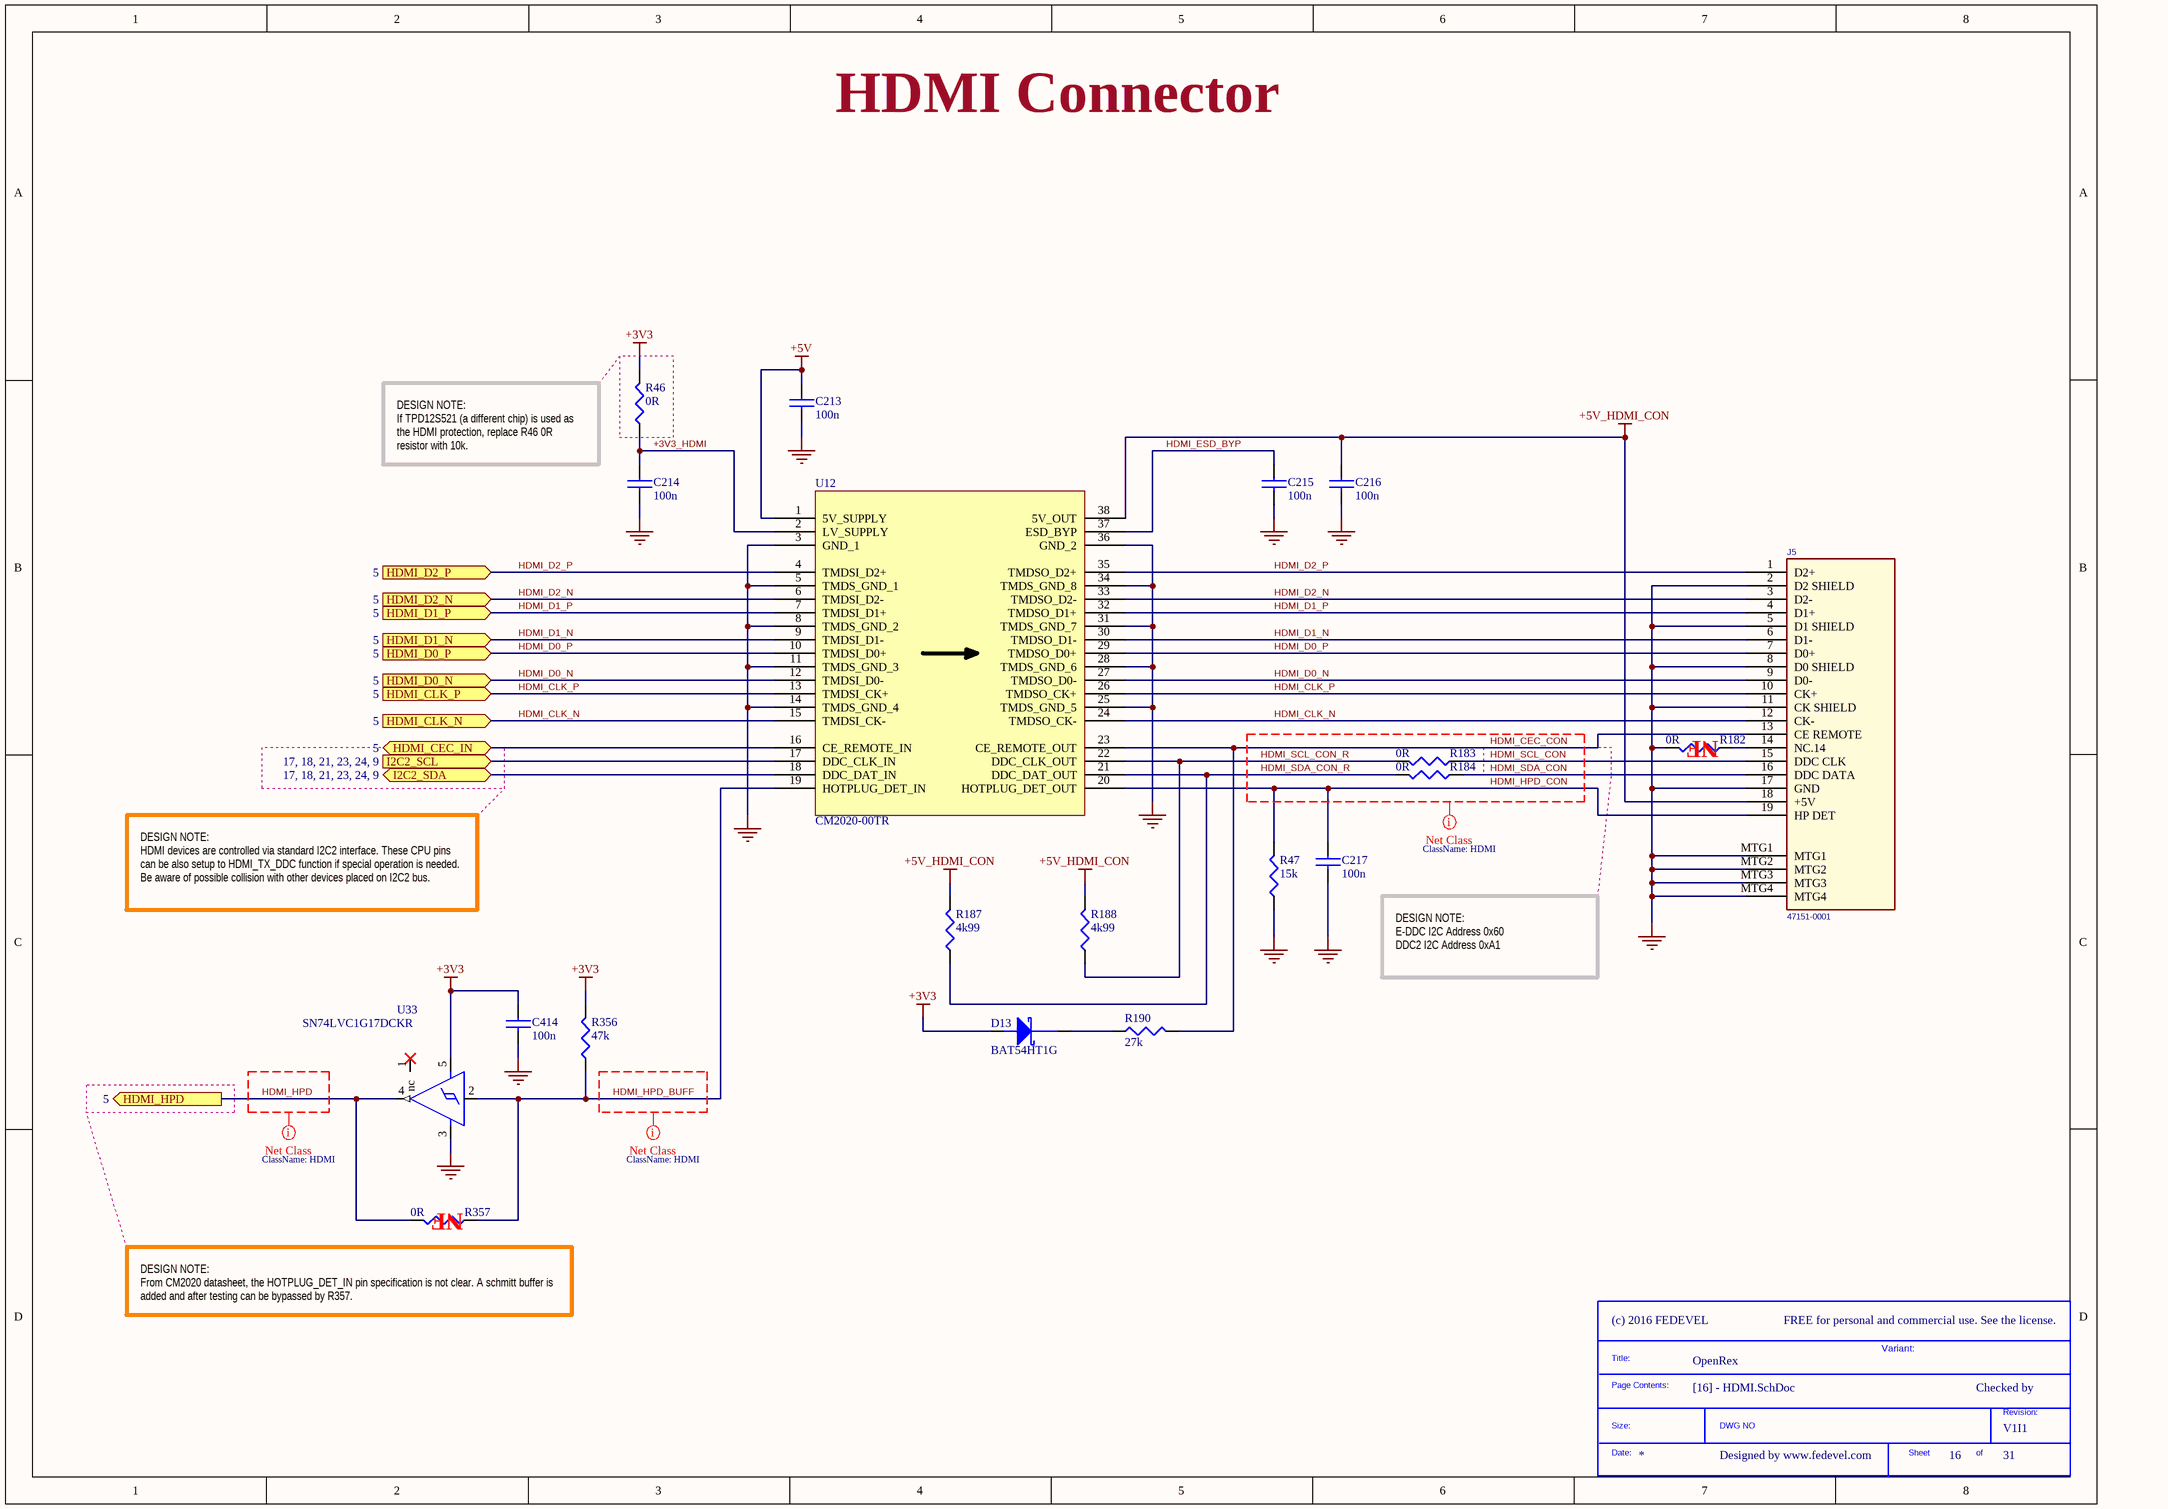
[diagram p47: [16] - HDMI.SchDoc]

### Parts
(Parts that share a designator on the sheet are numbered #1, #2 ... from top to bottom, then left to right.)
*#28  SDTitleBlock  (value not drawn)  (graphical)
C213  100n  [C0402]
C214  100n  [C0402]
C215  100n  [C0402]
C216  100n  [C0402]
C217  100n  [C0402]
C414  100n  [C0402]
D13  BAT54HT1G  [SOD323]
J5  47151-0001  [HDMI V1.1]
R46  0R  [R0402]
R47  15k  [R0402]
R182  0R  [R0402]
R183  0R  [R0402]
R184  0R  [R0402]
R187  4k99  [R0402]
R188  4k99  [R0402]
R190  27k  [R0402]
R356  47k  [R0402]
R357  0R  [R0402]
U12  CM2020-00TR  [TSSOP_38]
U33  SN74LVC1G17DCKR  [SC70_5]

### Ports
HDMI_CEC_IN (bidir, see 5), HDMI_CLK_N (in, see 5), HDMI_CLK_P (in, see 5), HDMI_D0_N (in, see 5), HDMI_D0_P (in, see 5), HDMI_D1_N (in, see 5), HDMI_D1_P (in, see 5), HDMI_D2_N (in, see 5), HDMI_D2_P (in, see 5), HDMI_HPD (out, see 5), I2C2_SCL (see 17, 18, 21, 23, 24, 9), I2C2_SDA (bidir, see 17, 18, 21, 23, 24, 9)

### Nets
+3V3: C414.1 D13.2(Anode) R46.2 R356.2 U33.5(NC1)
+5V: C213.1 U12.1(5V_SUPPLY)
+5V_HDMI_CON: C216.1 J5.18(+5V) R187.2 R188.2 U12.38(5V_OUT)
GND: C213.2 C214.2 C215.2 C216.2 C217.2 C414.2 J5.2(D2_SHIELD) J5.5(D1_SHIELD) J5.8(D0_SHIELD) J5.11(CK_SHIELD) J5.17(GND) J5.MTG1 J5.MTG2 J5.MTG3 J5.MTG4 R47.1 R182.2 U12.3(GND_1) U12.5(TMDS_GND_1) U12.8(TMDS_GND_2) U12.11(TMDS_GND_3) U12.14(TMDS_GND_4) U12.25(TMDS_GND_5) U12.28(TMDS_GND_6) U12.31(TMDS_GND_7) U12.34(TMDS_GND_8) U12.36(GND_2) U33.3(GND)
+3V3_HDMI: C214.1 R46.1 U12.2(LV_SUPPLY)
HDMI_CEC_CON: J5.13(CE_REMOTE) R190.2 U12.23(CE_REMOTE_OUT)
HDMI_CEC_IN: U12.16(CE_REMOTE_IN) ; port HDMI_CEC_IN
HDMI_CLK_N: J5.12(CK-) U12.15(TMDSI_CK-) U12.24(TMDSO_CK-) ; port HDMI_CLK_N
HDMI_CLK_P: J5.10(CK+) U12.13(TMDSI_CK+) U12.26(TMDSO_CK+) ; port HDMI_CLK_P
HDMI_D0_N: J5.9(D0-) U12.12(TMDSI_D0-) U12.27(TMDSO_D0-) ; port HDMI_D0_N
HDMI_D0_P: J5.7(D0+) U12.10(TMDSI_D0+) U12.29(TMDSO_D0+) ; port HDMI_D0_P
HDMI_D1_N: J5.6(D1-) U12.9(TMDSI_D1-) U12.30(TMDSO_D1-) ; port HDMI_D1_N
HDMI_D1_P: J5.4(D1+) U12.7(TMDSI_D1+) U12.32(TMDSO_D1+) ; port HDMI_D1_P
HDMI_D2_N: J5.3(D2-) U12.6(TMDSI_D2-) U12.33(TMDSO_D2-) ; port HDMI_D2_N
HDMI_D2_P: J5.1(D2+) U12.4(TMDSI_D2+) U12.35(TMDSO_D2+) ; port HDMI_D2_P
HDMI_ESD_BYP: C215.1 U12.37(ESD_BYP)
HDMI_HPD: R357.2 U33.4(O) ; port HDMI_HPD
HDMI_HPD_BUFF: R356.1 R357.1 U12.19(HOTPLUG_DET_IN) U33.2(I)
HDMI_HPD_CON: C217.1 J5.19(HP_DET) R47.2 U12.20(HOTPLUG_DET_OUT)
HDMI_SCL_CON: J5.15(DDC_CLK) R183.1
HDMI_SCL_CON_R: R183.2 R188.1 U12.22(DDC_CLK_OUT)
HDMI_SDA_CON: J5.16(DDC_DATA) R184.1
HDMI_SDA_CON_R: R184.2 R187.1 U12.21(DDC_DAT_OUT)
I2C2_SCL: U12.17(DDC_CLK_IN) ; port I2C2_SCL
I2C2_SDA: U12.18(DDC_DAT_IN) ; port I2C2_SDA
NetD13_1: D13.1(Cathode) R190.1
NetJ5_14: J5.14(NC.14) R182.1

Not connected (* = marked no-connect by the designer): U33 1(nc)*

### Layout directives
net class HDMI: HDMI_CEC_CON, HDMI_HPD, HDMI_HPD_BUFF, HDMI_HPD_CON, HDMI_SCL_CON, HDMI_SCL_CON_R, HDMI_SDA_CON, HDMI_SDA_CON_R

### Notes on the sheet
- HDMI Connector
- DESIGN NOTE:
  If TPD12S521 (a different chip) is used as the HDMI protection, replace R46 0R resistor with 10k.
- DESIGN NOTE:
  HDMI devices are controlled via standard I2C2 interface. These CPU pins can be also setup to HDMI_TX_DDC function if special operation is needed. Be aware of possible collision with other devices placed on I2C2 bus.
- DESIGN NOTE:
  E-DDC I2C Address 0x60
  DDC2 I2C Address 0xA1
- (near R357) DESIGN NOTE:
  From CM2020 datasheet, the HOTPLUG_DET_IN pin specification is not clear. A schmitt buffer is added and after testing can be bypassed by R357.
- FREE for personal and commercial use. See the license.
- Variant:
- Checked by
- Designed by www.fedevel.com

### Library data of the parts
C213-C217 C414 = C1005X5R1H104K: as C230 on sheet [28] - PWR IN, MECH, DOC
D13 = BAT54HT1G: DIODE SCHOTTKY 30V 0.2A SOD323; Manufacturer: Fairchild Semiconductor; Current - Average Rectified (Io): 200mA; Voltage - Forward (Vf) (Max) @ If: 800mV @ 100mA; Speed: Small Signal =< 200mA (Io), Any Speed; Reverse Recovery Time (trr): 5ns; Current - Reverse Leakage @ Vr: 2µA @ 25V; Capacitance @ Vr, F: 10pF @ 1V, 1MHz; Thermal Resistance: 600°C/W Ja; .Creator: MM; .Checked PCB: used
J5 = 47151-0001_v1.1: CONN RCPT 19POS HDMI RT ANG SMD; Manufacturer: Molex Connector Corporation; .Checked PCB: MM; Number of Positions: 19; Pitch: 0.50mm (.020"); Gender: Receptacle; .Version: V1.1 - Changed holes to slots
R46 R182-R184 R357 = RC0402JR-070RL: as R155 on sheet [28] - PWR IN, MECH, DOC
R47 = RC0402FR-0715KL: RES 15.0K OHM 1/16W 1% 0402 SMD; Manufacturer: Yageo; Power (Watts): 0.063W, 1/16W; .Checked PCB: used; Temperature Coefficient: ±100ppm/°C
R187 R188 = RMCF0402FT4K99: RES TF 4.99K OHM 1% 1/16W 0402; Manufacturer: Stackpole Electronics Inc; Power (Watts): 0.063W, 1/16W; .Checked PCB: used; Temperature Coefficient: ±100ppm/°C
R190 = RC0402FR-0727KL: RES 27.0K OHM 1/16W 1% 0402 SMD; Manufacturer: Yageo; Power (Watts): 0.063W, 1/16W; .Checked PCB: used; Temperature Coefficient: ±100ppm/°C
R356 = RC0402FR-0747KL: RES 47.0K OHM 1/16W 1% 0402 SMD; Manufacturer: Yageo; Power (Watts): 0.063W, 1/16W; .Checked PCB: used; Temperature Coefficient: ±100ppm/°C
U12 = CM2020-00TR: IC HDMI TX PORT P/I 38-TSSOP; Manufacturer: ON Semiconductor; .Creator: MM; .Checked PCB: used
U33 = SN74LVC1G17DCKR: IC BUFFER SCHMIT TRIG SC705; Manufacturer: Texas Instruments; Logic Type: Schmitt Trigger - Buffer, Driver; Number of Elements: 1; Current - Output High, Low: 32mA, 32mA; Voltage - Supply: 1.65 V ~ 5.5 V; .Checked PCB: RF

## Sheet [21] - AUDIO.SchDoc
size A3; DocumentNumber: 21; SheetNumber: 21; SheetTotal: 31
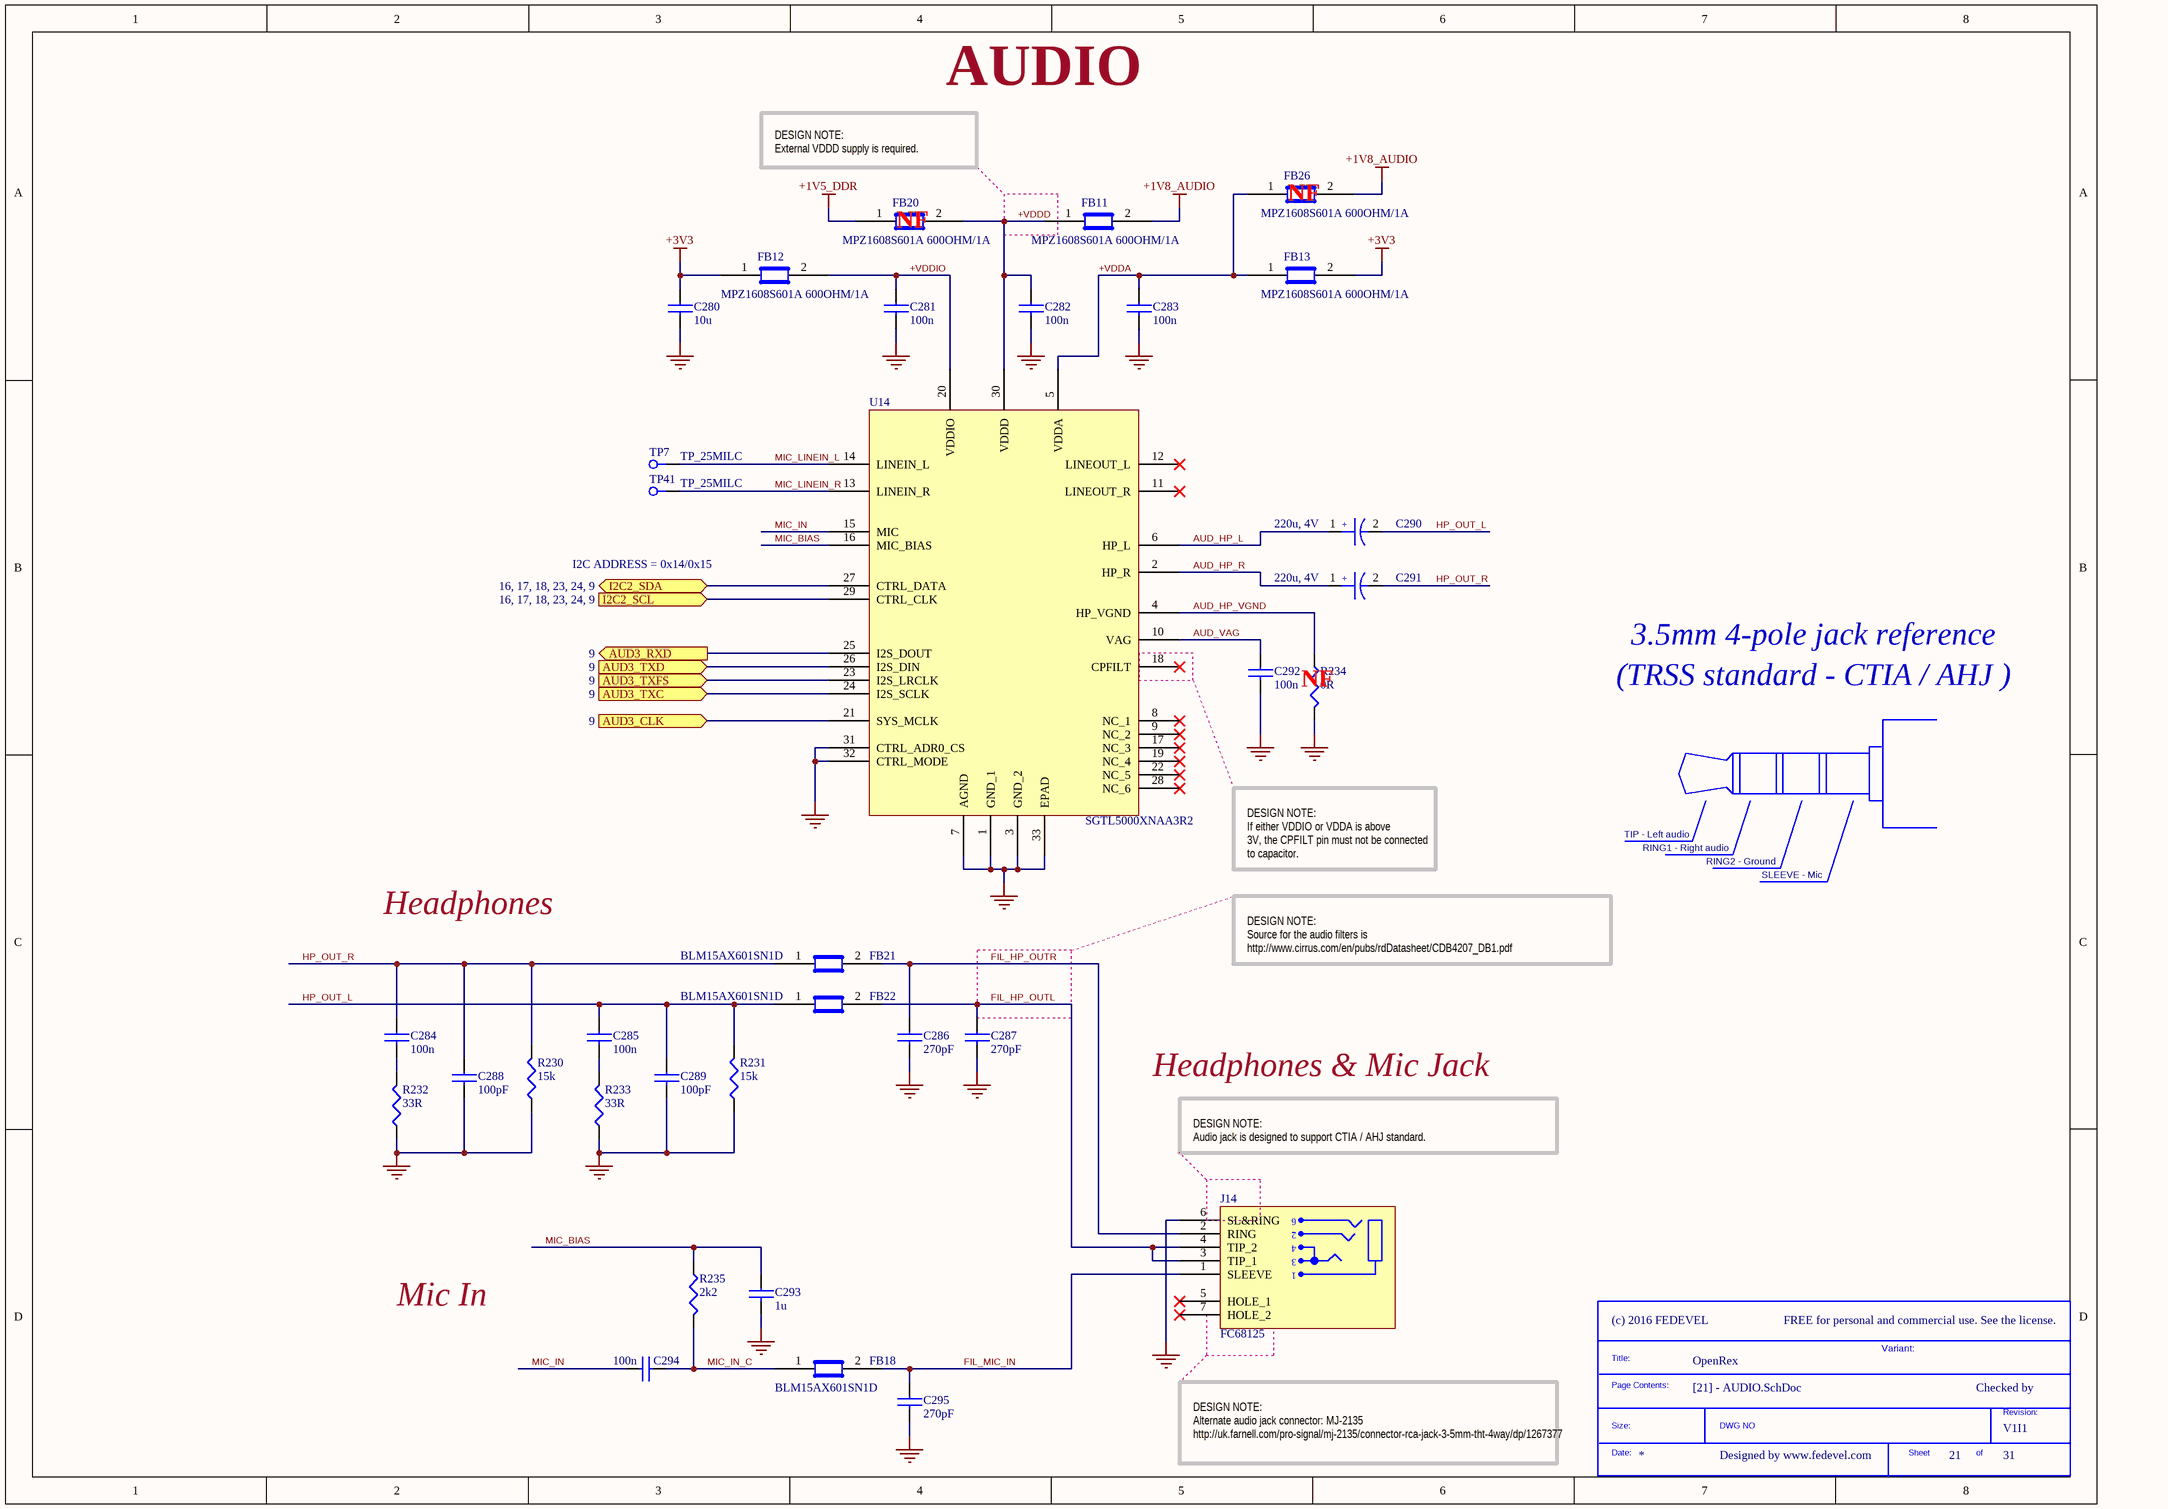
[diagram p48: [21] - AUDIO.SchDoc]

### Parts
(Parts that share a designator on the sheet are numbered #1, #2 ... from top to bottom, then left to right.)
*#29  SDTitleBlock  (value not drawn)  (graphical)
C280  10u  [C0603]
C281  100n  [C0402]
C282  100n  [C0402]
C283  100n  [C0402]
C284  100n  [C0402]
C285  100n  [C0402]
C286  270pF  [C0402]
C287  270pF  [C0402]
C288  100pF  [C0402]
C289  100pF  [C0402]
C290  220u, 4V  [C1206 -  TLN S Case Tantal]
C291  220u, 4V  [C1206 -  TLN S Case Tantal]
C292  100n  [C0402]
C293  1u  [C0402]
C294  100n  [C0402]
C295  270pF  [C0402]
FB11  MPZ1608S601A 600OHM/1A  [C0603]
FB12  MPZ1608S601A 600OHM/1A  [C0603]
FB13  MPZ1608S601A 600OHM/1A  [C0603]
FB18  BLM15AX601SN1D  [C0402]
FB20  MPZ1608S601A 600OHM/1A  [C0603]
FB21  BLM15AX601SN1D  [C0402]
FB22  BLM15AX601SN1D  [C0402]
FB26  MPZ1608S601A 600OHM/1A  [C0603]
J14  FC68125  [FC68125]
R230  15k  [R0402]
R231  15k  [R0402]
R232  33R  [R0402]
R233  33R  [R0402]
R234  0R  [R0402]
R235  2k2  [R0402]
TP7  TP_25MILC  [TP_25C]  (no BOM)
TP41  TP_25MILC  [TP_25C]  (no BOM)
U14  SGTL5000XNAA3R2  [QFN32 5x5x0.85_V1.1]

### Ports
AUD3_CLK (in, see 9), AUD3_RXD (out, see 9), AUD3_TXC (in, see 9), AUD3_TXD (in, see 9), AUD3_TXFS (in, see 9), I2C2_SCL (see 16, 17, 18, 23, 24, 9), I2C2_SDA (bidir, see 16, 17, 18, 23, 24, 9)

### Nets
+1V5_DDR: FB20.1
+1V8_AUDIO: FB11.2 FB26.2
+3V3: C280.1 FB12.1 FB13.2
GND: C280.2 C281.2 C282.2 C283.2 C286.2 C287.2 C288.2 C289.2 C292.2 C293.2 C295.2 J14.6(SL&RING) R230.1 R231.1 R232.1 R233.1 R234.2 U14.1(GND_1) U14.3(GND_2) U14.7(AGND) U14.31(CTRL_ADR0_CS) U14.32(CTRL_MODE) U14.33(EPAD)
+VDDA: C283.1 FB13.1 FB26.1 U14.5(VDDA)
+VDDD: C282.1 FB11.1 FB20.2 U14.30(VDDD)
+VDDIO: C281.1 FB12.2 U14.20(VDDIO)
AUD3_CLK: U14.21(SYS_MCLK) ; port AUD3_CLK
AUD3_RXD: U14.25(I2S_DOUT) ; port AUD3_RXD
AUD3_TXC: U14.24(I2S_SCLK) ; port AUD3_TXC
AUD3_TXD: U14.26(I2S_DIN) ; port AUD3_TXD
AUD3_TXFS: U14.23(I2S_LRCLK) ; port AUD3_TXFS
AUD_HP_L: C290.1 U14.6(HP_L)
AUD_HP_R: C291.1 U14.2(HP_R)
AUD_HP_VGND: R234.1 U14.4(HP_VGND)
AUD_VAG: C292.1 U14.10(VAG)
FIL_HP_OUTL: C287.1 FB22.2 J14.3(TIP_1) J14.4(TIP_2)
FIL_HP_OUTR: C286.1 FB21.2 J14.2(RING)
FIL_MIC_IN: C295.1 FB18.2 J14.1(SLEEVE)
HP_OUT_L: C285.1 C289.1 C290.2 FB22.1 R231.2
HP_OUT_R: C284.1 C288.1 C291.2 FB21.1 R230.2
I2C2_SCL: U14.29(CTRL_CLK) ; port I2C2_SCL
I2C2_SDA: U14.27(CTRL_DATA) ; port I2C2_SDA
MIC_BIAS: C293.1 R235.1 U14.16(MIC_BIAS)
MIC_IN: C294.1 U14.15(MIC)
MIC_IN_C: C294.2 FB18.1 R235.2
MIC_LINEIN_L: TP7.1 U14.14(LINEIN_L)
MIC_LINEIN_R: TP41.1 U14.13(LINEIN_R)
NetC284_2: C284.2 R232.2
NetC285_2: C285.2 R233.2

Not connected (* = marked no-connect by the designer): J14 5(HOLE_1)* 7(HOLE_2)*; U14 8(NC_1)* 9(NC_2)* 11(LINEOUT_R)* 12(LINEOUT_L)* 17(NC_3)* 18(CPFILT)* 19(NC_4)* 22(NC_5)* 28(NC_6)*

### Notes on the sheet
- AUDIO
- DESIGN NOTE:
  External VDDD supply is required.
- I2C ADDRESS = 0x14/0x15
- 3.5mm 4-pole jack reference
- (TRSS standard - CTIA / AHJ )
- TIP - Left audio
- RING1 - Right audio
- RING2 - Ground
- Headphones
- DESIGN NOTE:
  If either VDDIO or VDDA is above
  3V, the CPFILT pin must not be connected to capacitor.
- SLEEVE - Mic
- DESIGN NOTE:
  Source for the audio filters is http://www.cirrus.com/en/pubs/rdDatasheet/CDB4207_DB1.pdf
- Headphones & Mic Jack
- DESIGN NOTE:
  Audio jack is designed to support CTIA / AHJ standard.
- Mic In
- FREE for personal and commercial use. See the license.
- Variant:
- Checked by
- DESIGN NOTE:
  Alternate audio jack connector: MJ-2135
  http://uk.farnell.com/pro-signal/mj-2135/connector-rca-jack-3-5mm-tht-4way/dp/1267377
- Designed by www.fedevel.com

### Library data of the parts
C280 = C1608X5R0J106M: CAP CER 10UF 6.3V X5R 20% 0603; Manufacturer: TDK Corporation; Capacitance: 10µF; Value: 10µF; .Checked PCB: used
C281-C285 C292 C294 = C1005X5R1H104K: as C230 on sheet [28] - PWR IN, MECH, DOC
C286 C287 C295 = GRM155R71H271KA01D: CAP CER 270PF 50V 10% X7R 0402; Manufacturer: Murata Electronics North America; .Checked PCB: used
C288 C289 = C1005C0G1H101J: as C311 on sheet [23] - SENSORS, CAN, IR
C290 C291 = TLNS227M004R3000: CAP TANT 220UF 4V 20% 1206; Manufacturer: AVX Corporation; Manufacturer Size Code: S; Capacitance: 220µF; ESR (Equivalent Series Resistance): 3.000 Ohm; Type: Molded; .Checked PCB: used
C293 = C1005X5R1C105K: as C326 on sheet [23] - SENSORS, CAN, IR
FB11-FB13 FB20 FB26 = MPZ1608S601A: as FB33 on sheet [23] - SENSORS, CAN, IR
FB18 FB21 FB22 = BLM15AX601SN1D: as FB43 on sheet [23] - SENSORS, CAN, IR
J14 = FC68125: CLIFF ELECTRONIC COMPONENTS - FC68125 - CONNECTOR, PHONO, 3.5MM, JACK, 4POLE; .Creator: MM
R230 R231 = RC0402FR-0715KL: as R47 on sheet [16] - HDMI
R232 R233 = RMCF0402FT33R0: RES TF 33 OHM 1% 1/16W 0402; Manufacturer: Stackpole Electronics Inc; Resistance (Ohms): 33; Power (Watts): 0.063W, 1/16W; .Checked PCB: used; Temperature Coefficient: ±100ppm/°C
R234 = RC0402JR-070RL: as R155 on sheet [28] - PWR IN, MECH, DOC
R235 = RC0402FR-072K2L: RES 2.20K OHM 1/16W 1% 0402 SMD; Manufacturer: Yageo; Resistance (Ohms): 2.2K; Power (Watts): 0.063W, 1/16W; .Checked PCB: used; Temperature Coefficient: ±100ppm/°C
TP7 TP41 = TP_25MILC: Test Point 25mil
U14 = SGTL5000XNAA3R2: IC AUDIO CODEC STEREO 32-QFN; Manufacturer: Freescale Semiconductor; Data Interface: I²C, Serial, SPI™; Number of ADCs / DACs: 1 / 1; Sigma Delta: No; S/N Ratio, ADCs / DACs (db) Typ: 90 / 100; Voltage - Supply, Analog: 1.62 V ~ 3.6 V; Voltage - Supply, Digital: 1.1 V ~ 2 V, 1.62 V ~ 3.6 V; .Creator: MM; .Checked PCB: used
